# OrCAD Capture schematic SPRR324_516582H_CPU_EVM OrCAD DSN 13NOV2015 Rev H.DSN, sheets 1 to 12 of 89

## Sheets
1 SH01 - TITLE PAGE: title: VAYU EVM; rev: H; note: 516582-0001
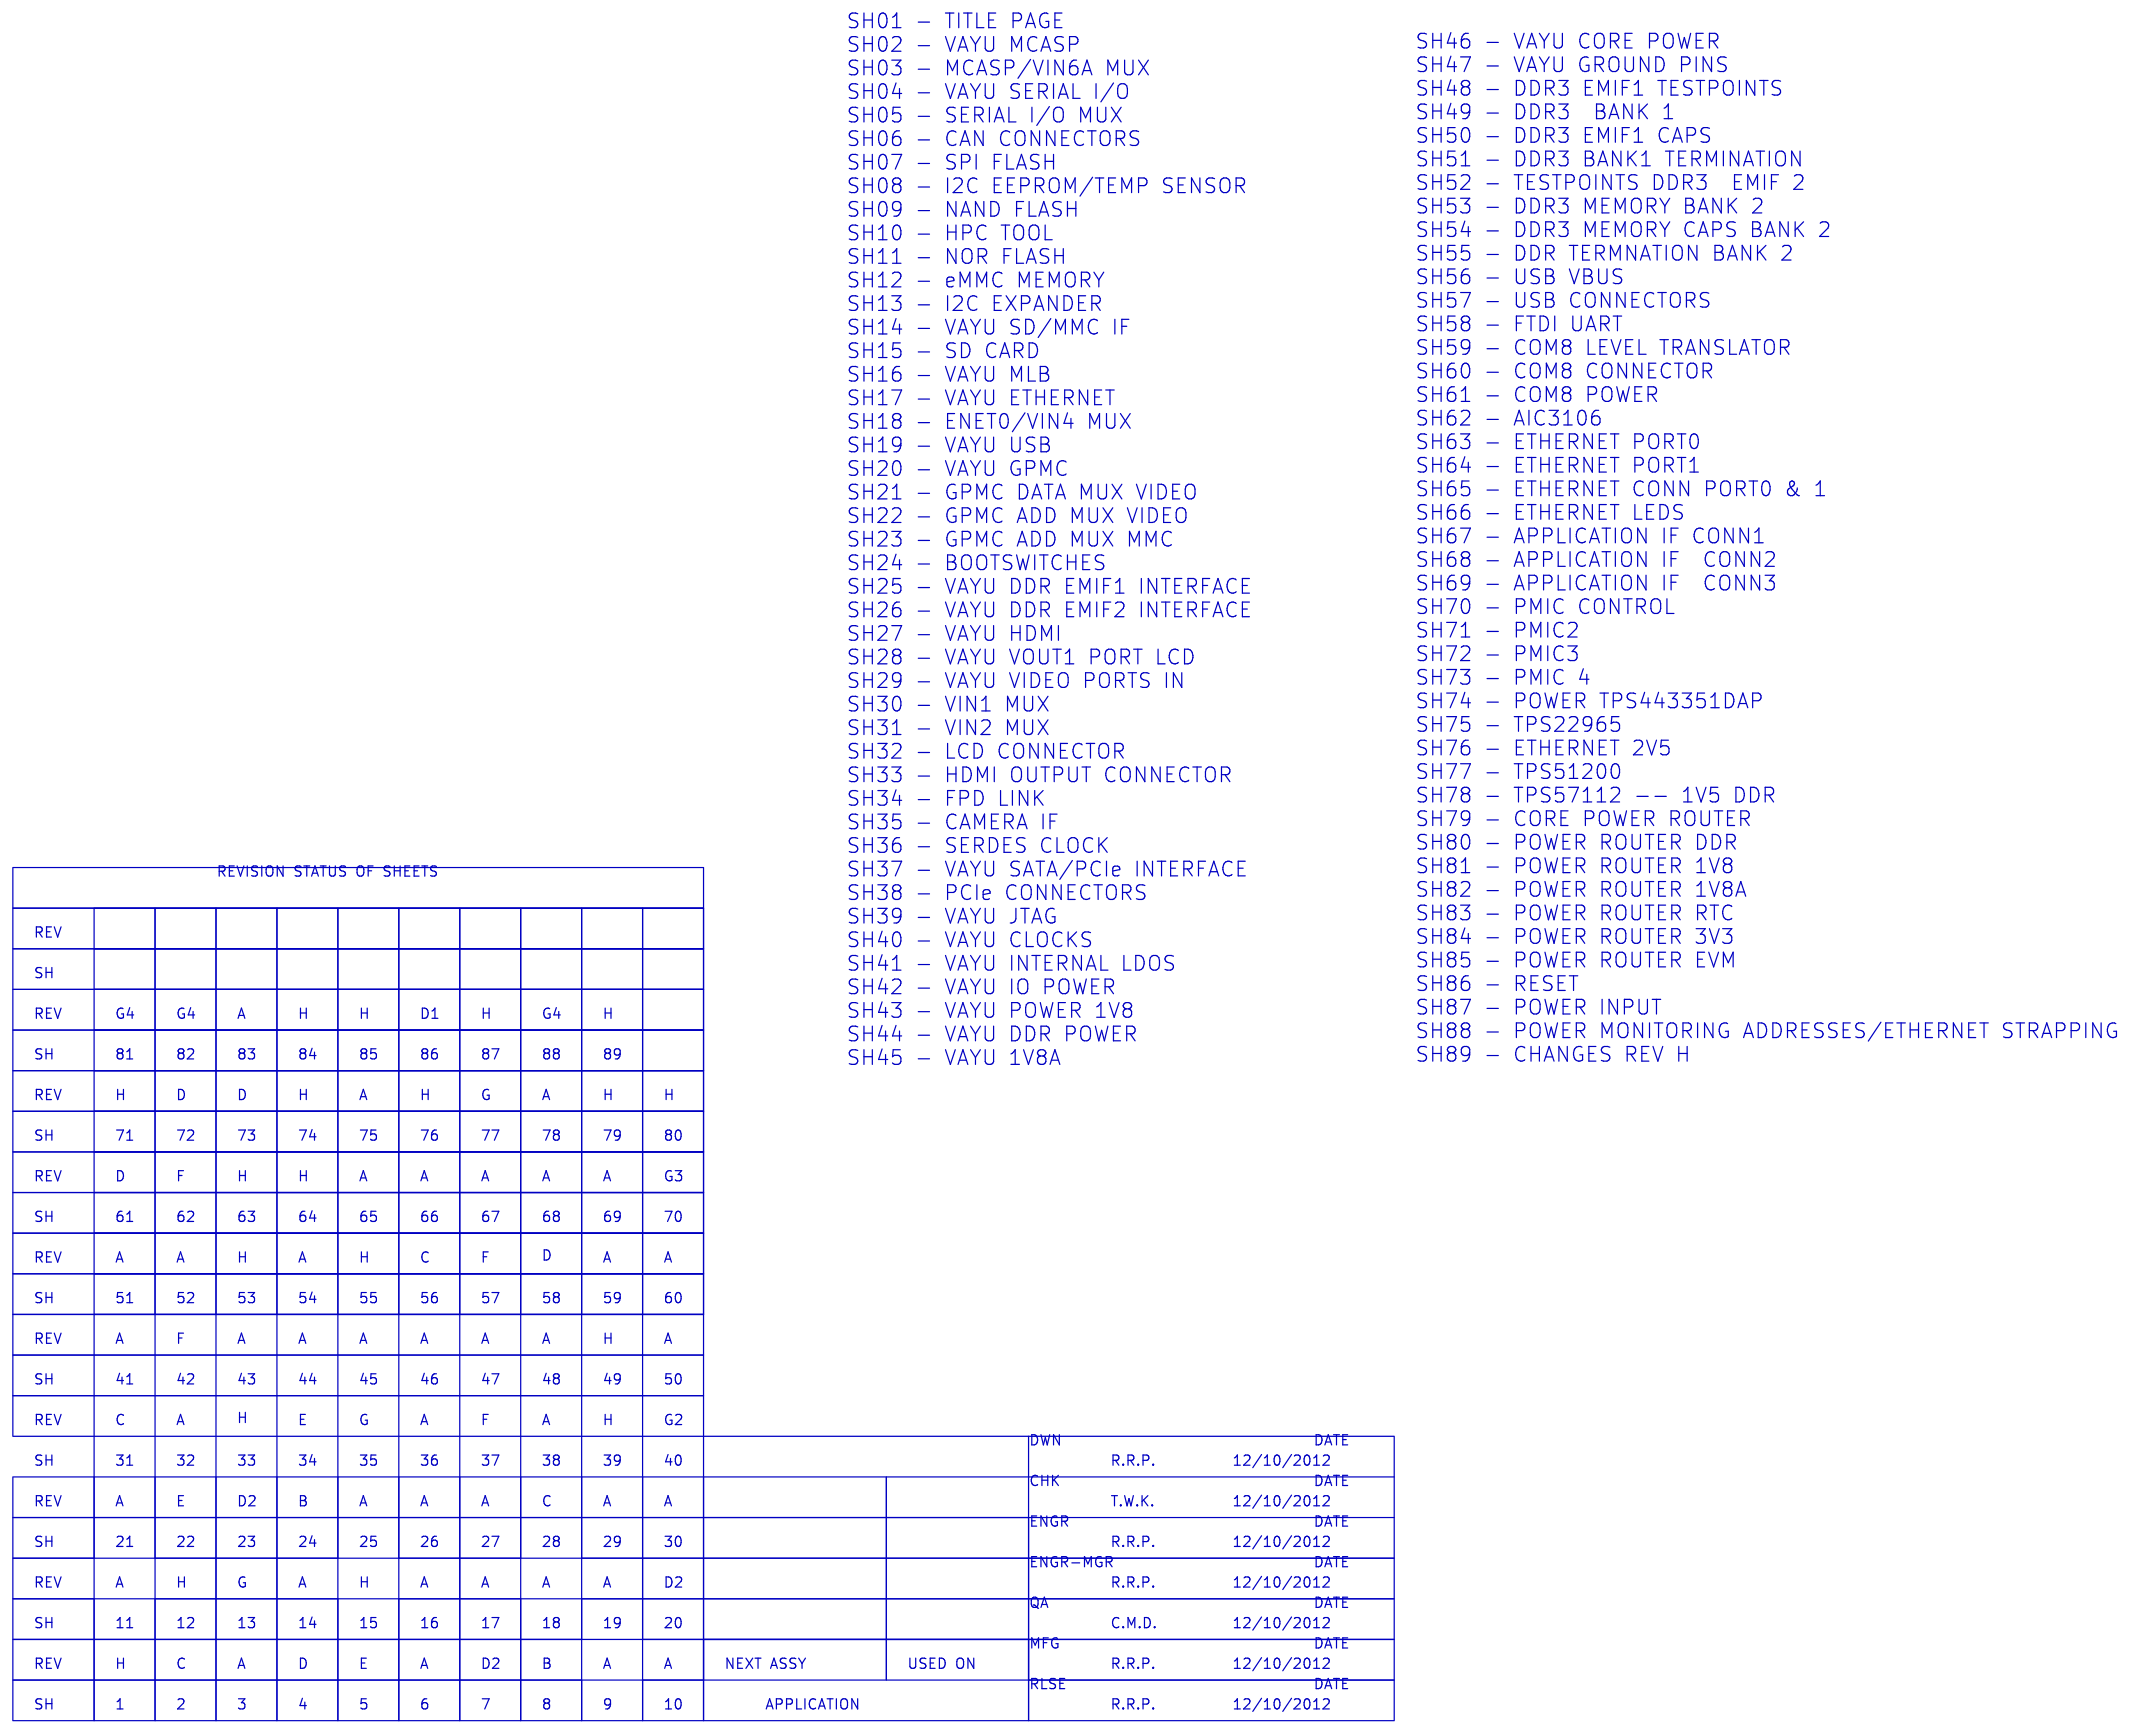
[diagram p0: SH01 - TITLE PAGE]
2 SH02 - VAYU MCASP: size B; rev: C
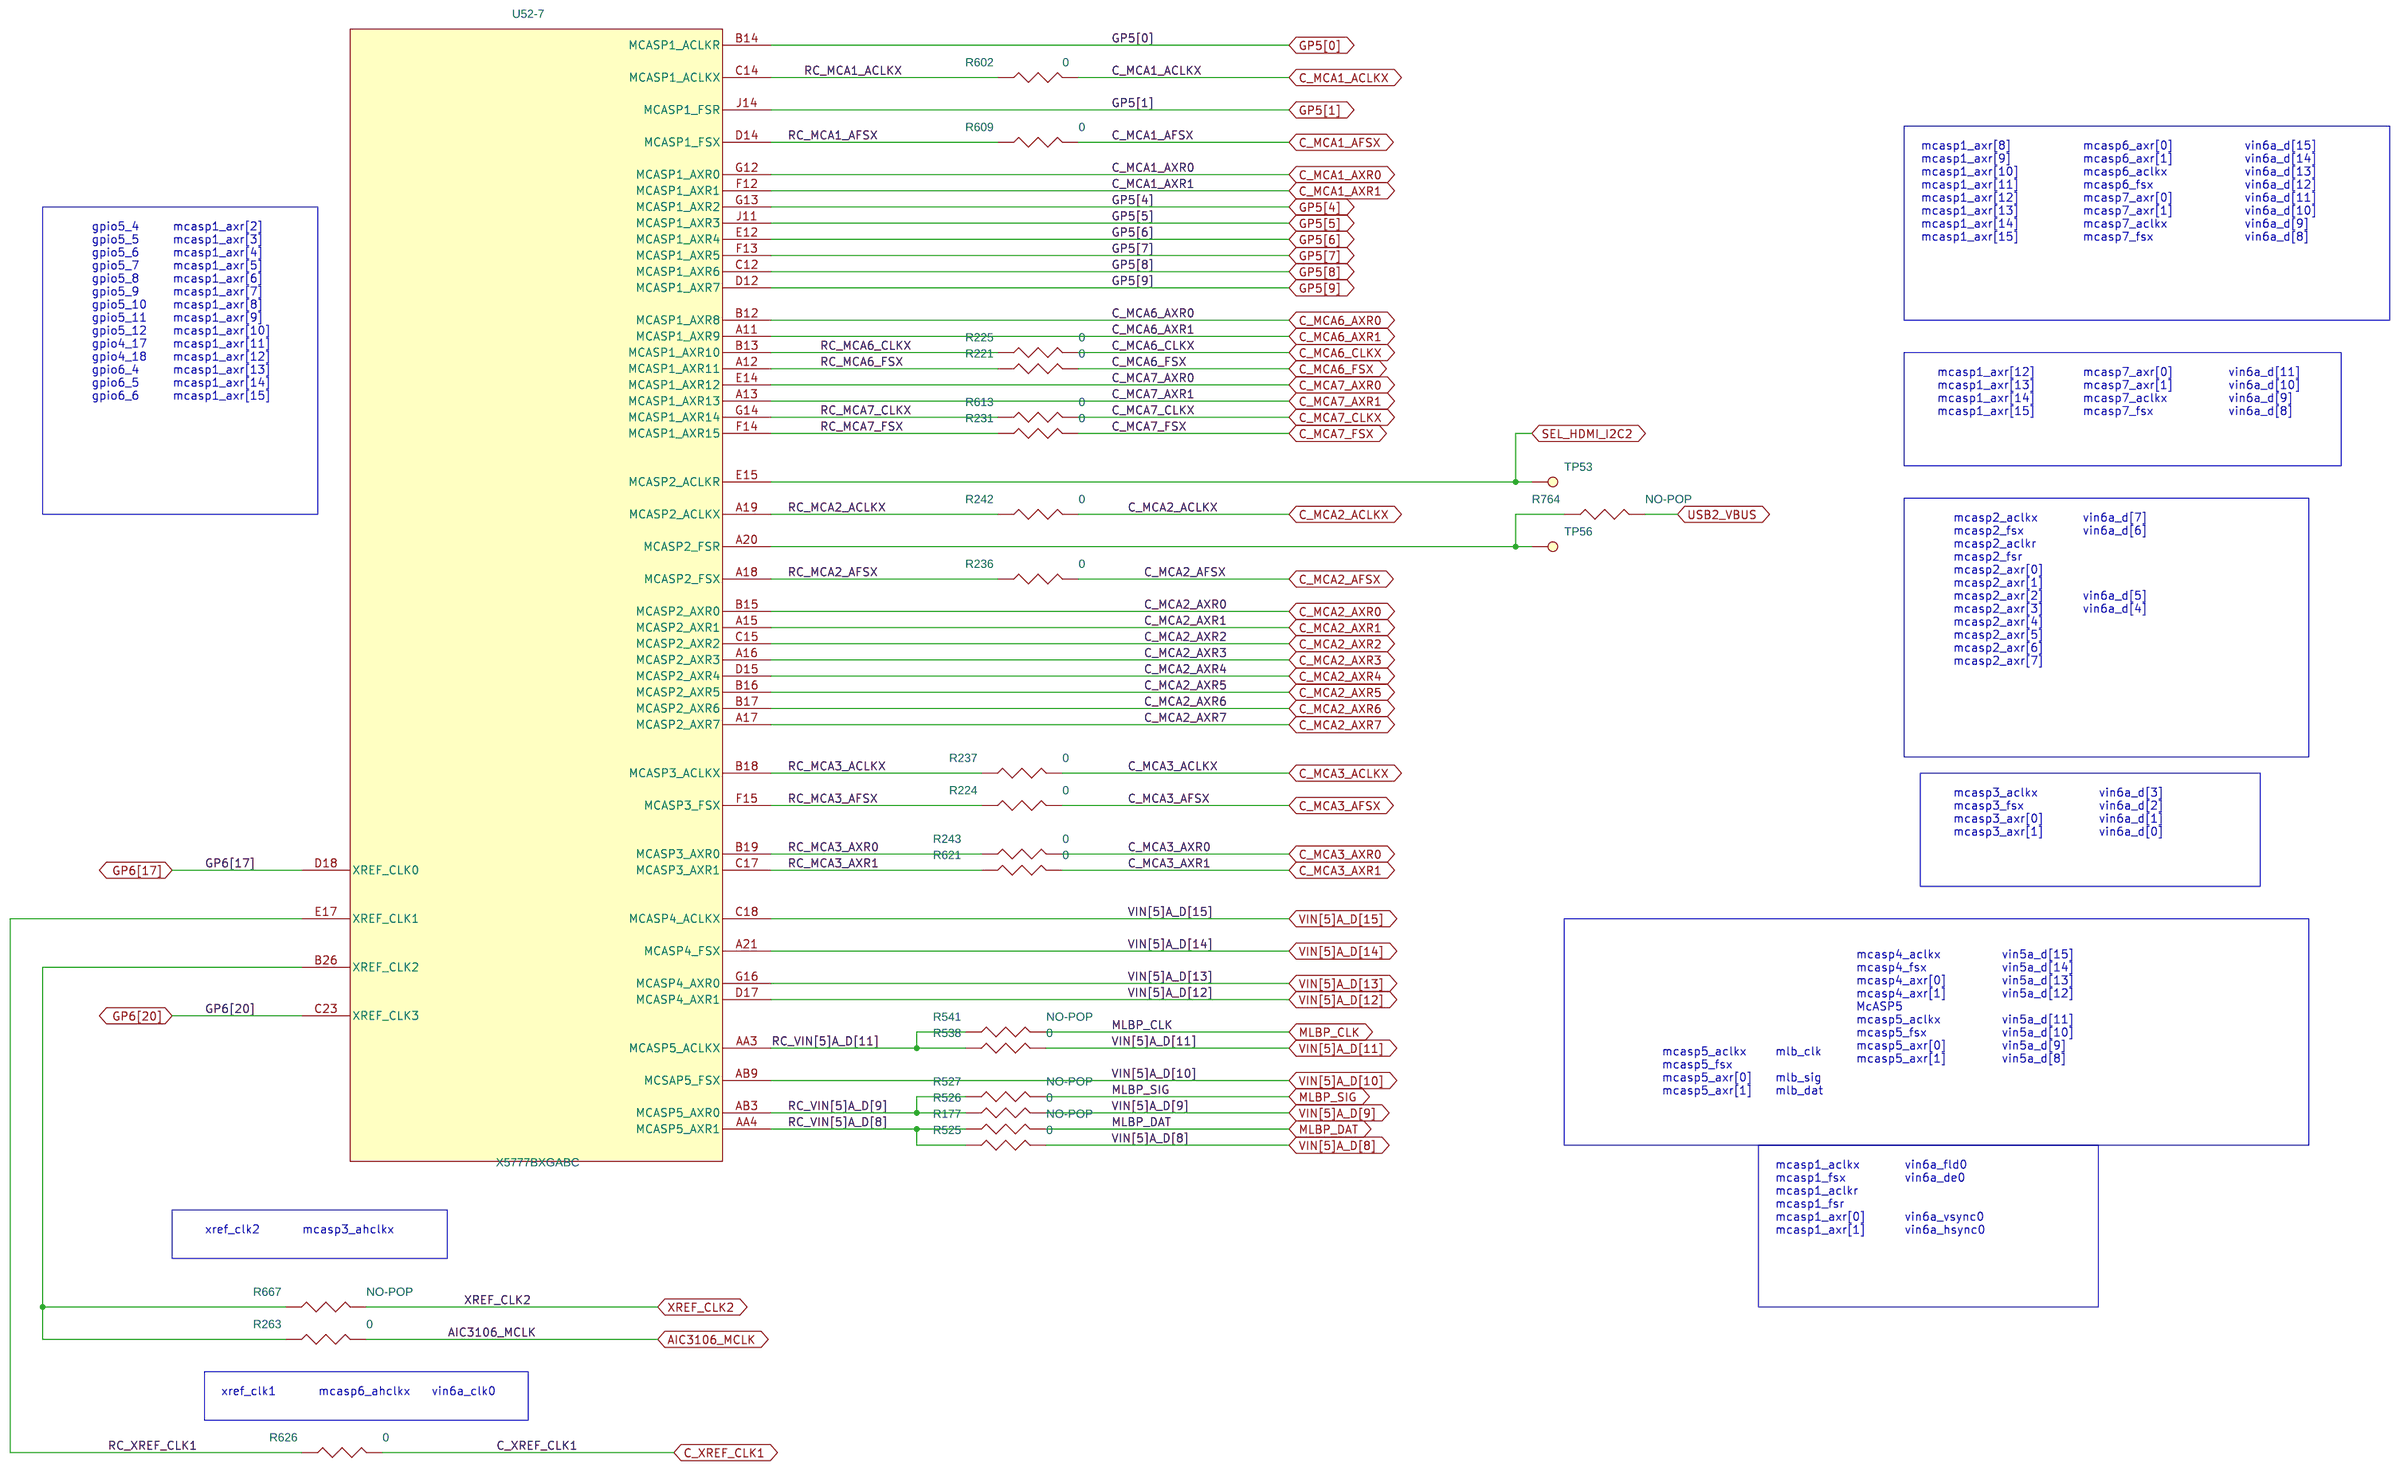
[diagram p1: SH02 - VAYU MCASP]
3 SH06 - CAN CONNECTORS: size B; rev: A
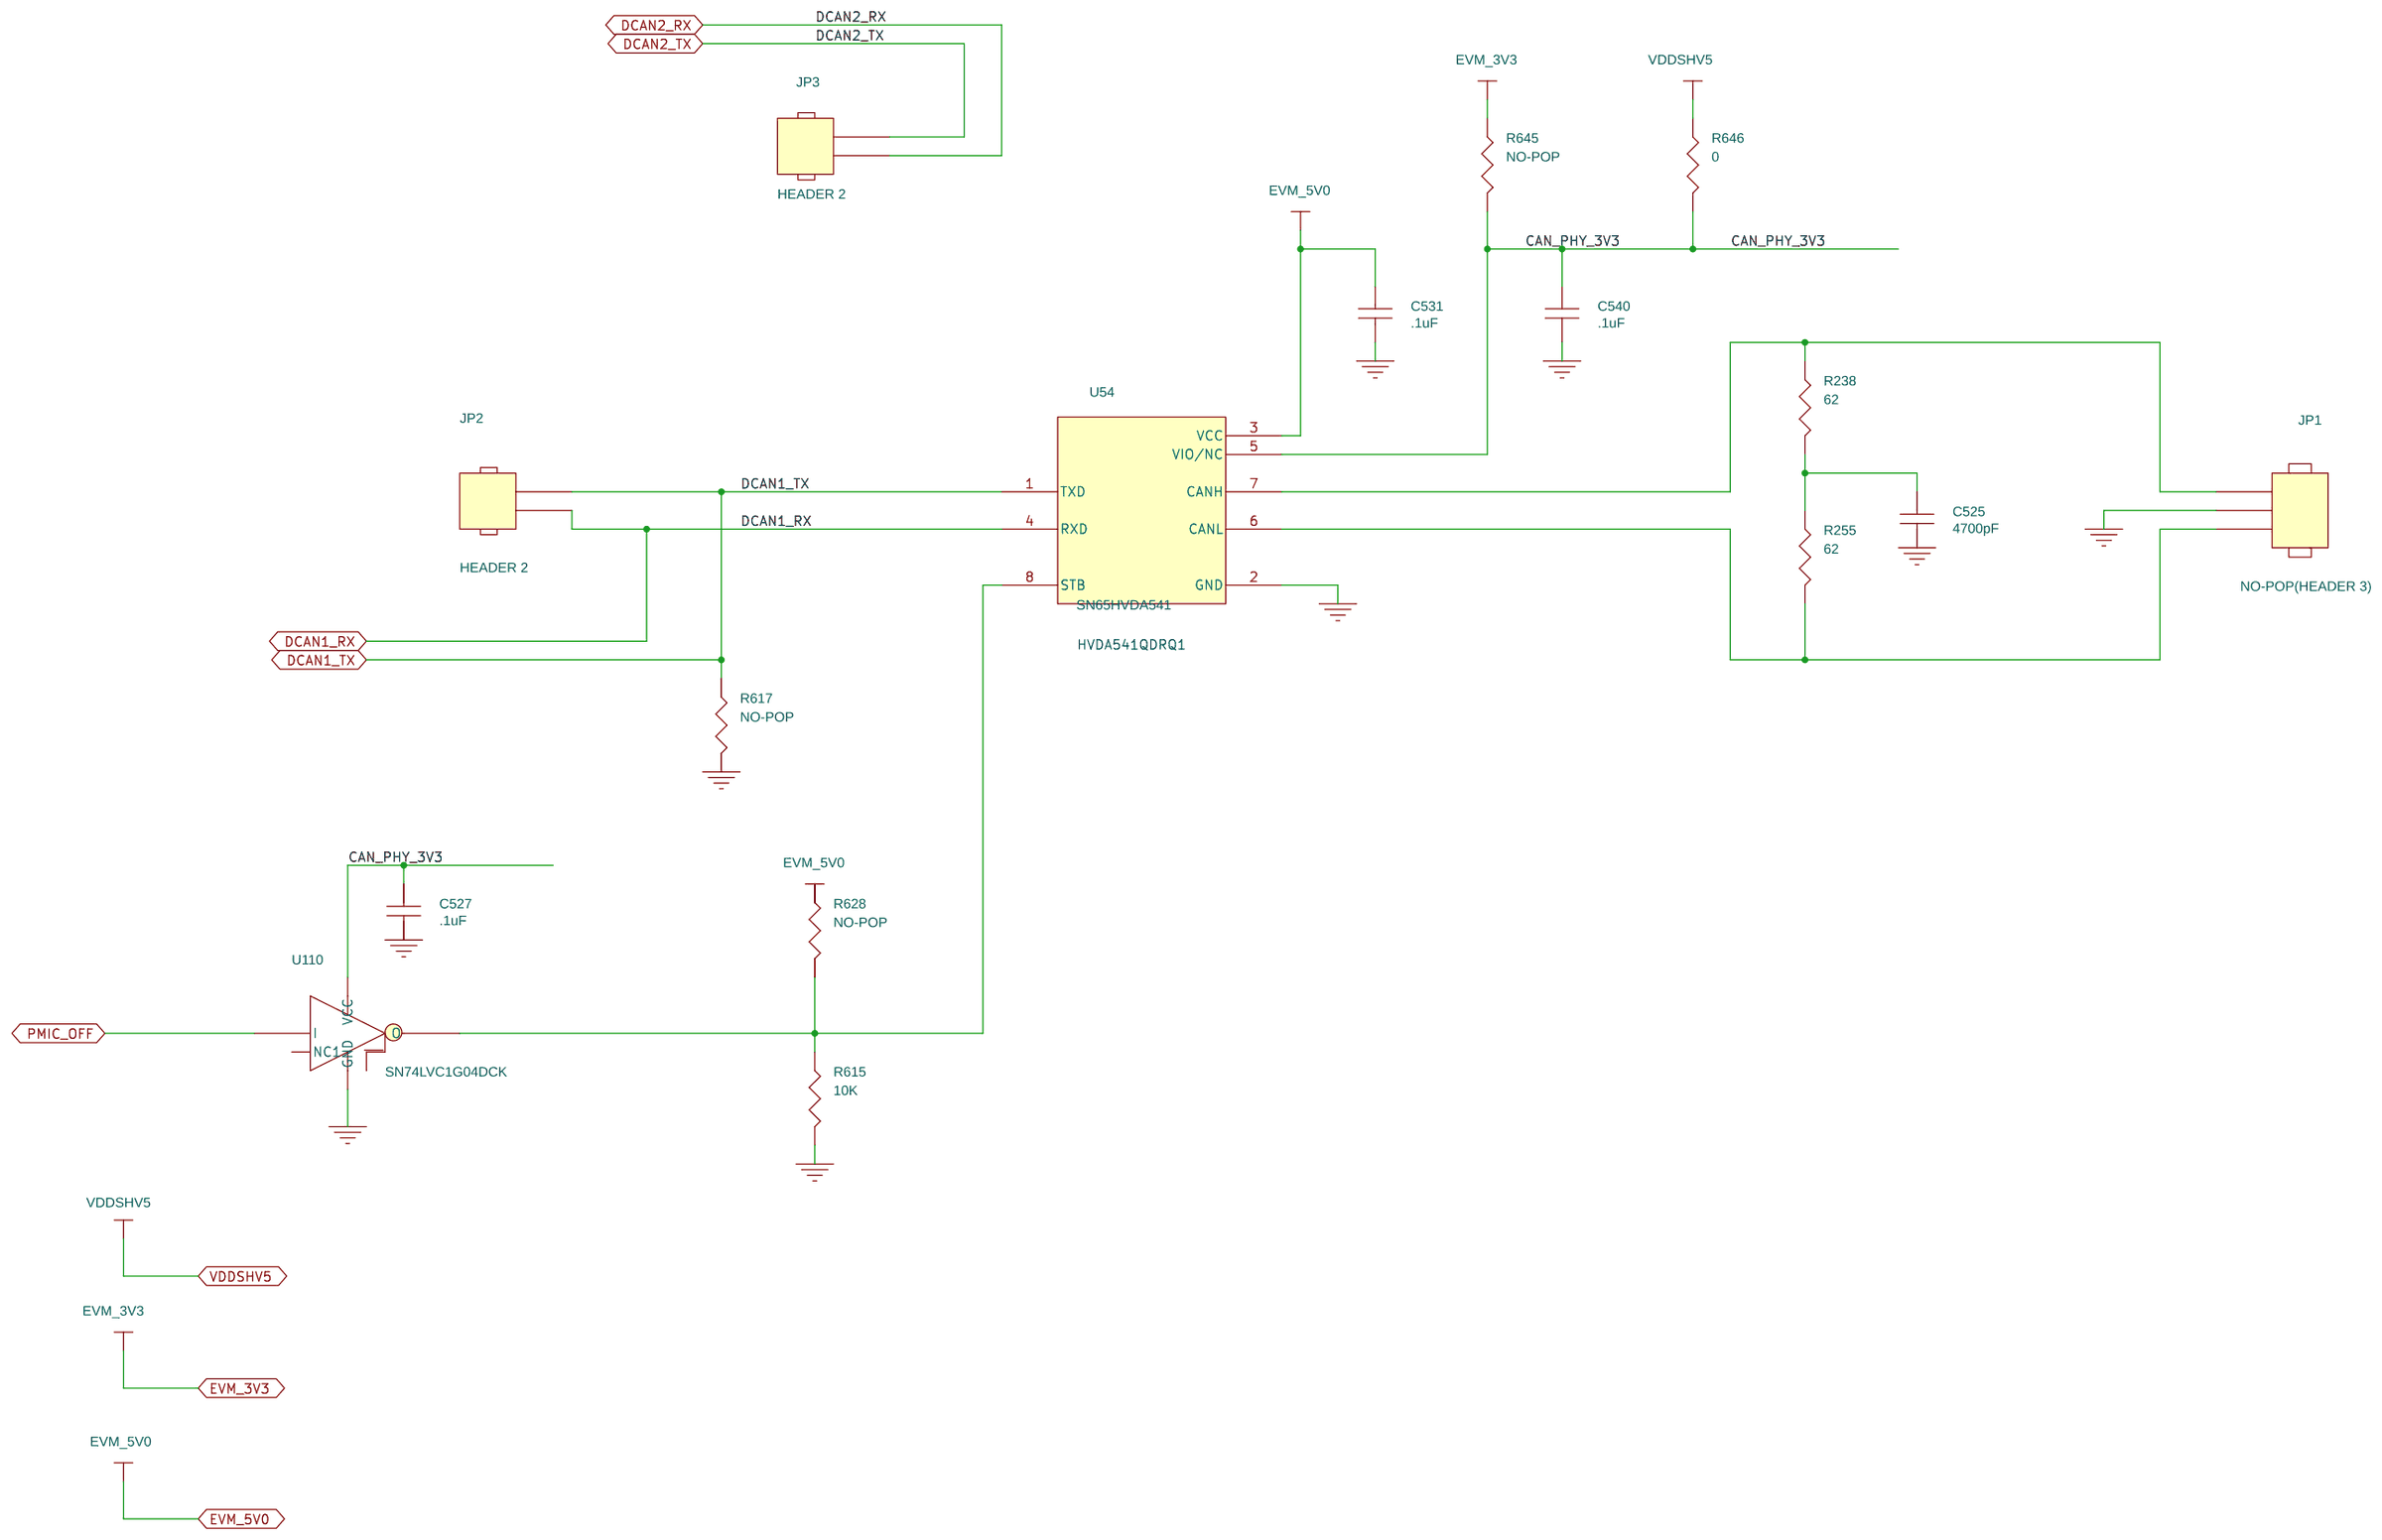
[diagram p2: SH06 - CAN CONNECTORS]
4 SH07 - SPI FLASH: size B; rev: D2
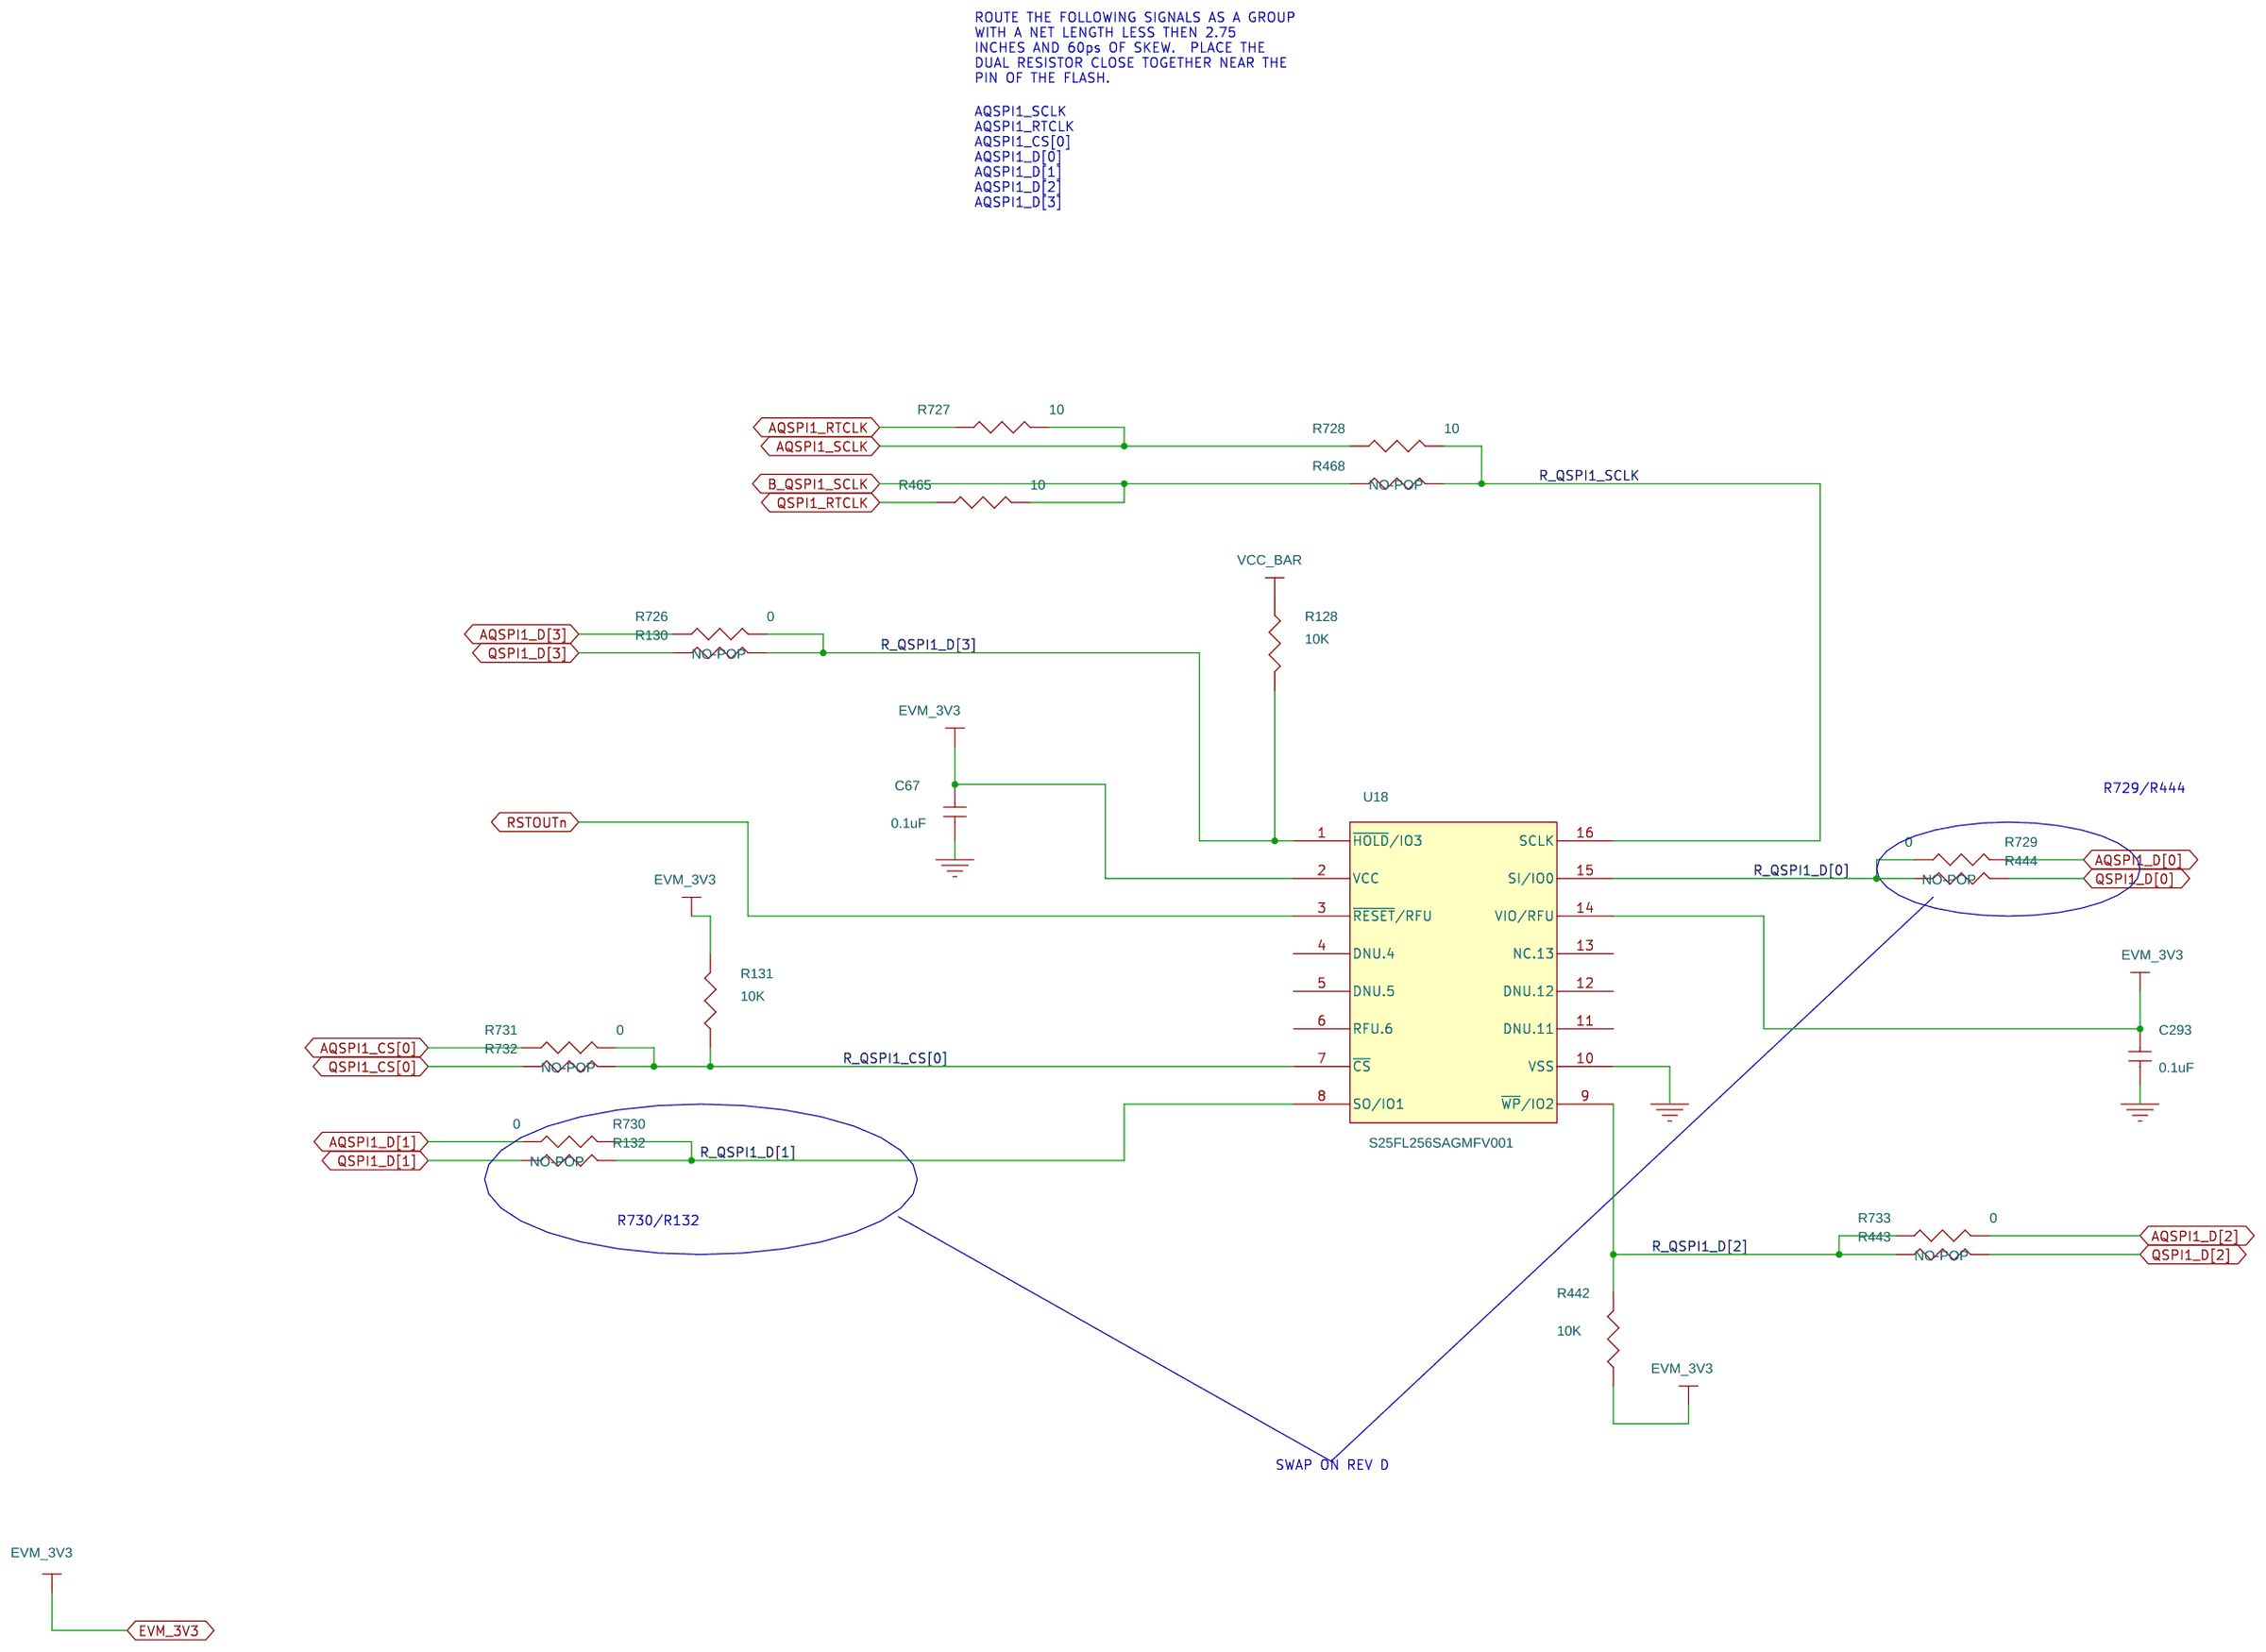
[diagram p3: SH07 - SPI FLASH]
5 SH09 - NAND FLASH: size B; rev: A
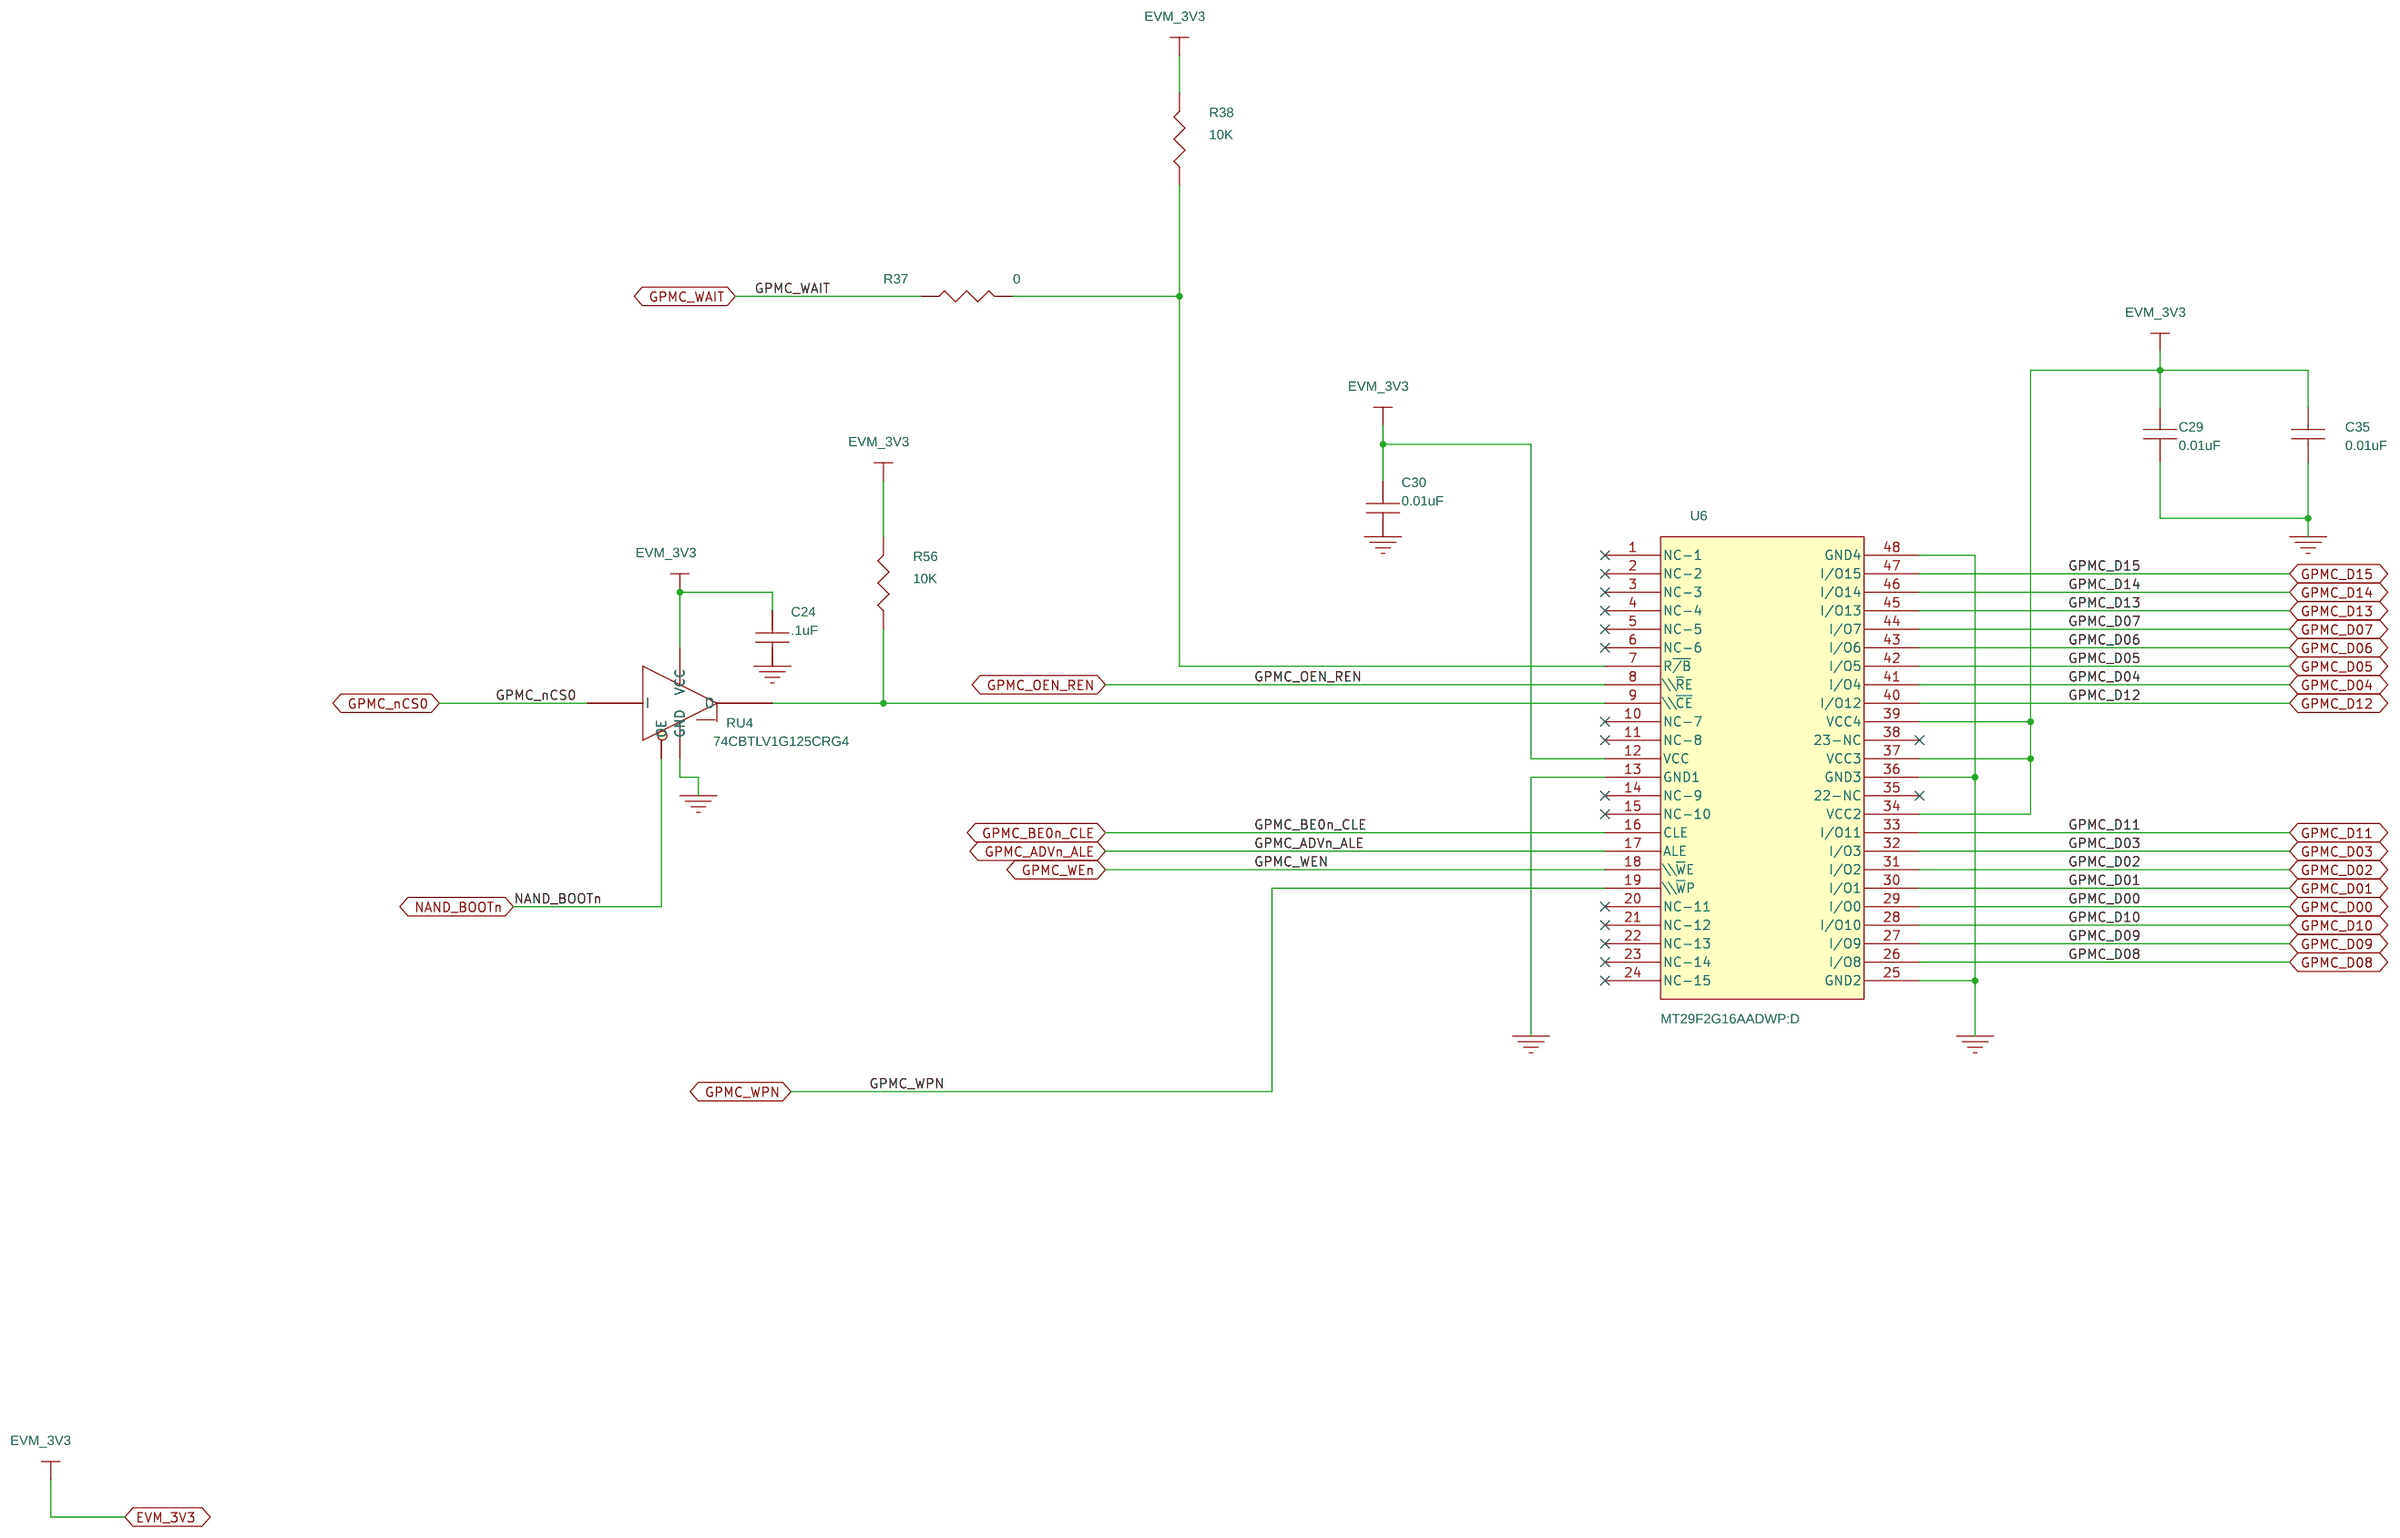
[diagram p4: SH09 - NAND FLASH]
6 SH10 - HPC TOOL: rev: A
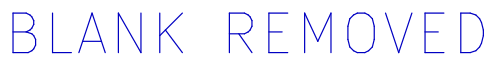
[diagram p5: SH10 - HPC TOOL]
7 SH11 - NOR FLASH: size B; rev: A
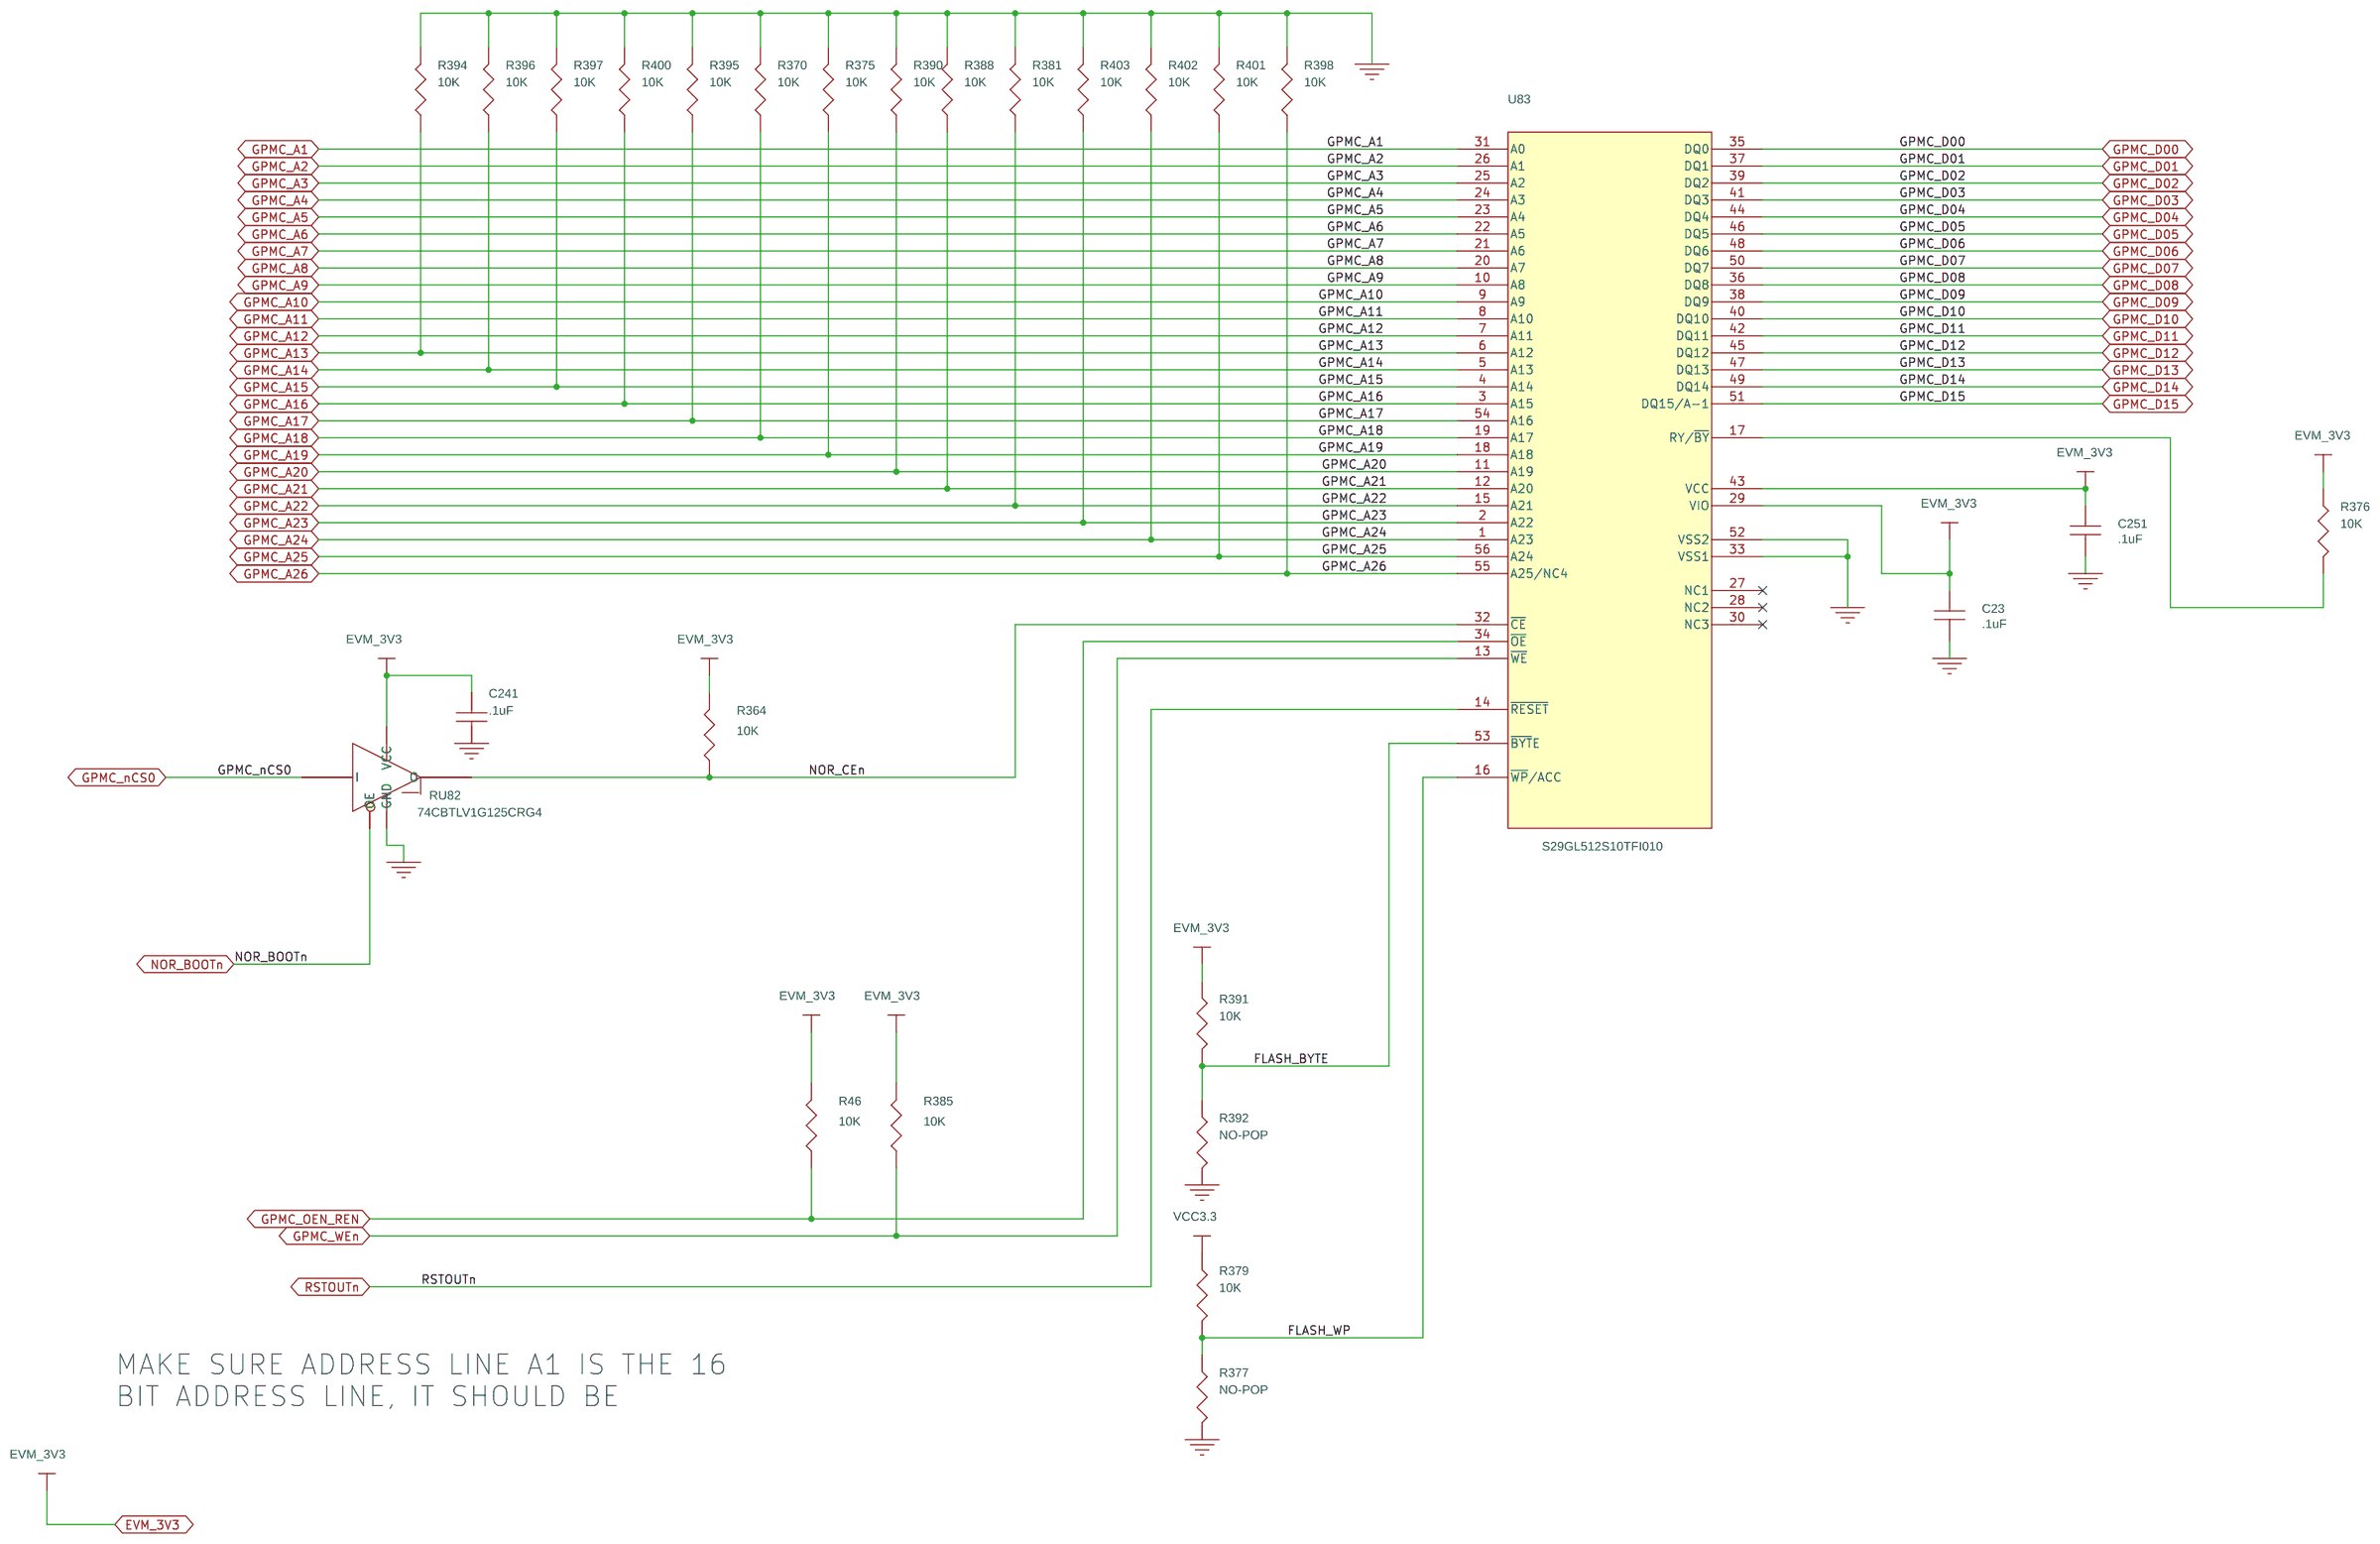
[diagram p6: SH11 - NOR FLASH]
8 SH12 - eMMC MEMORY: size B
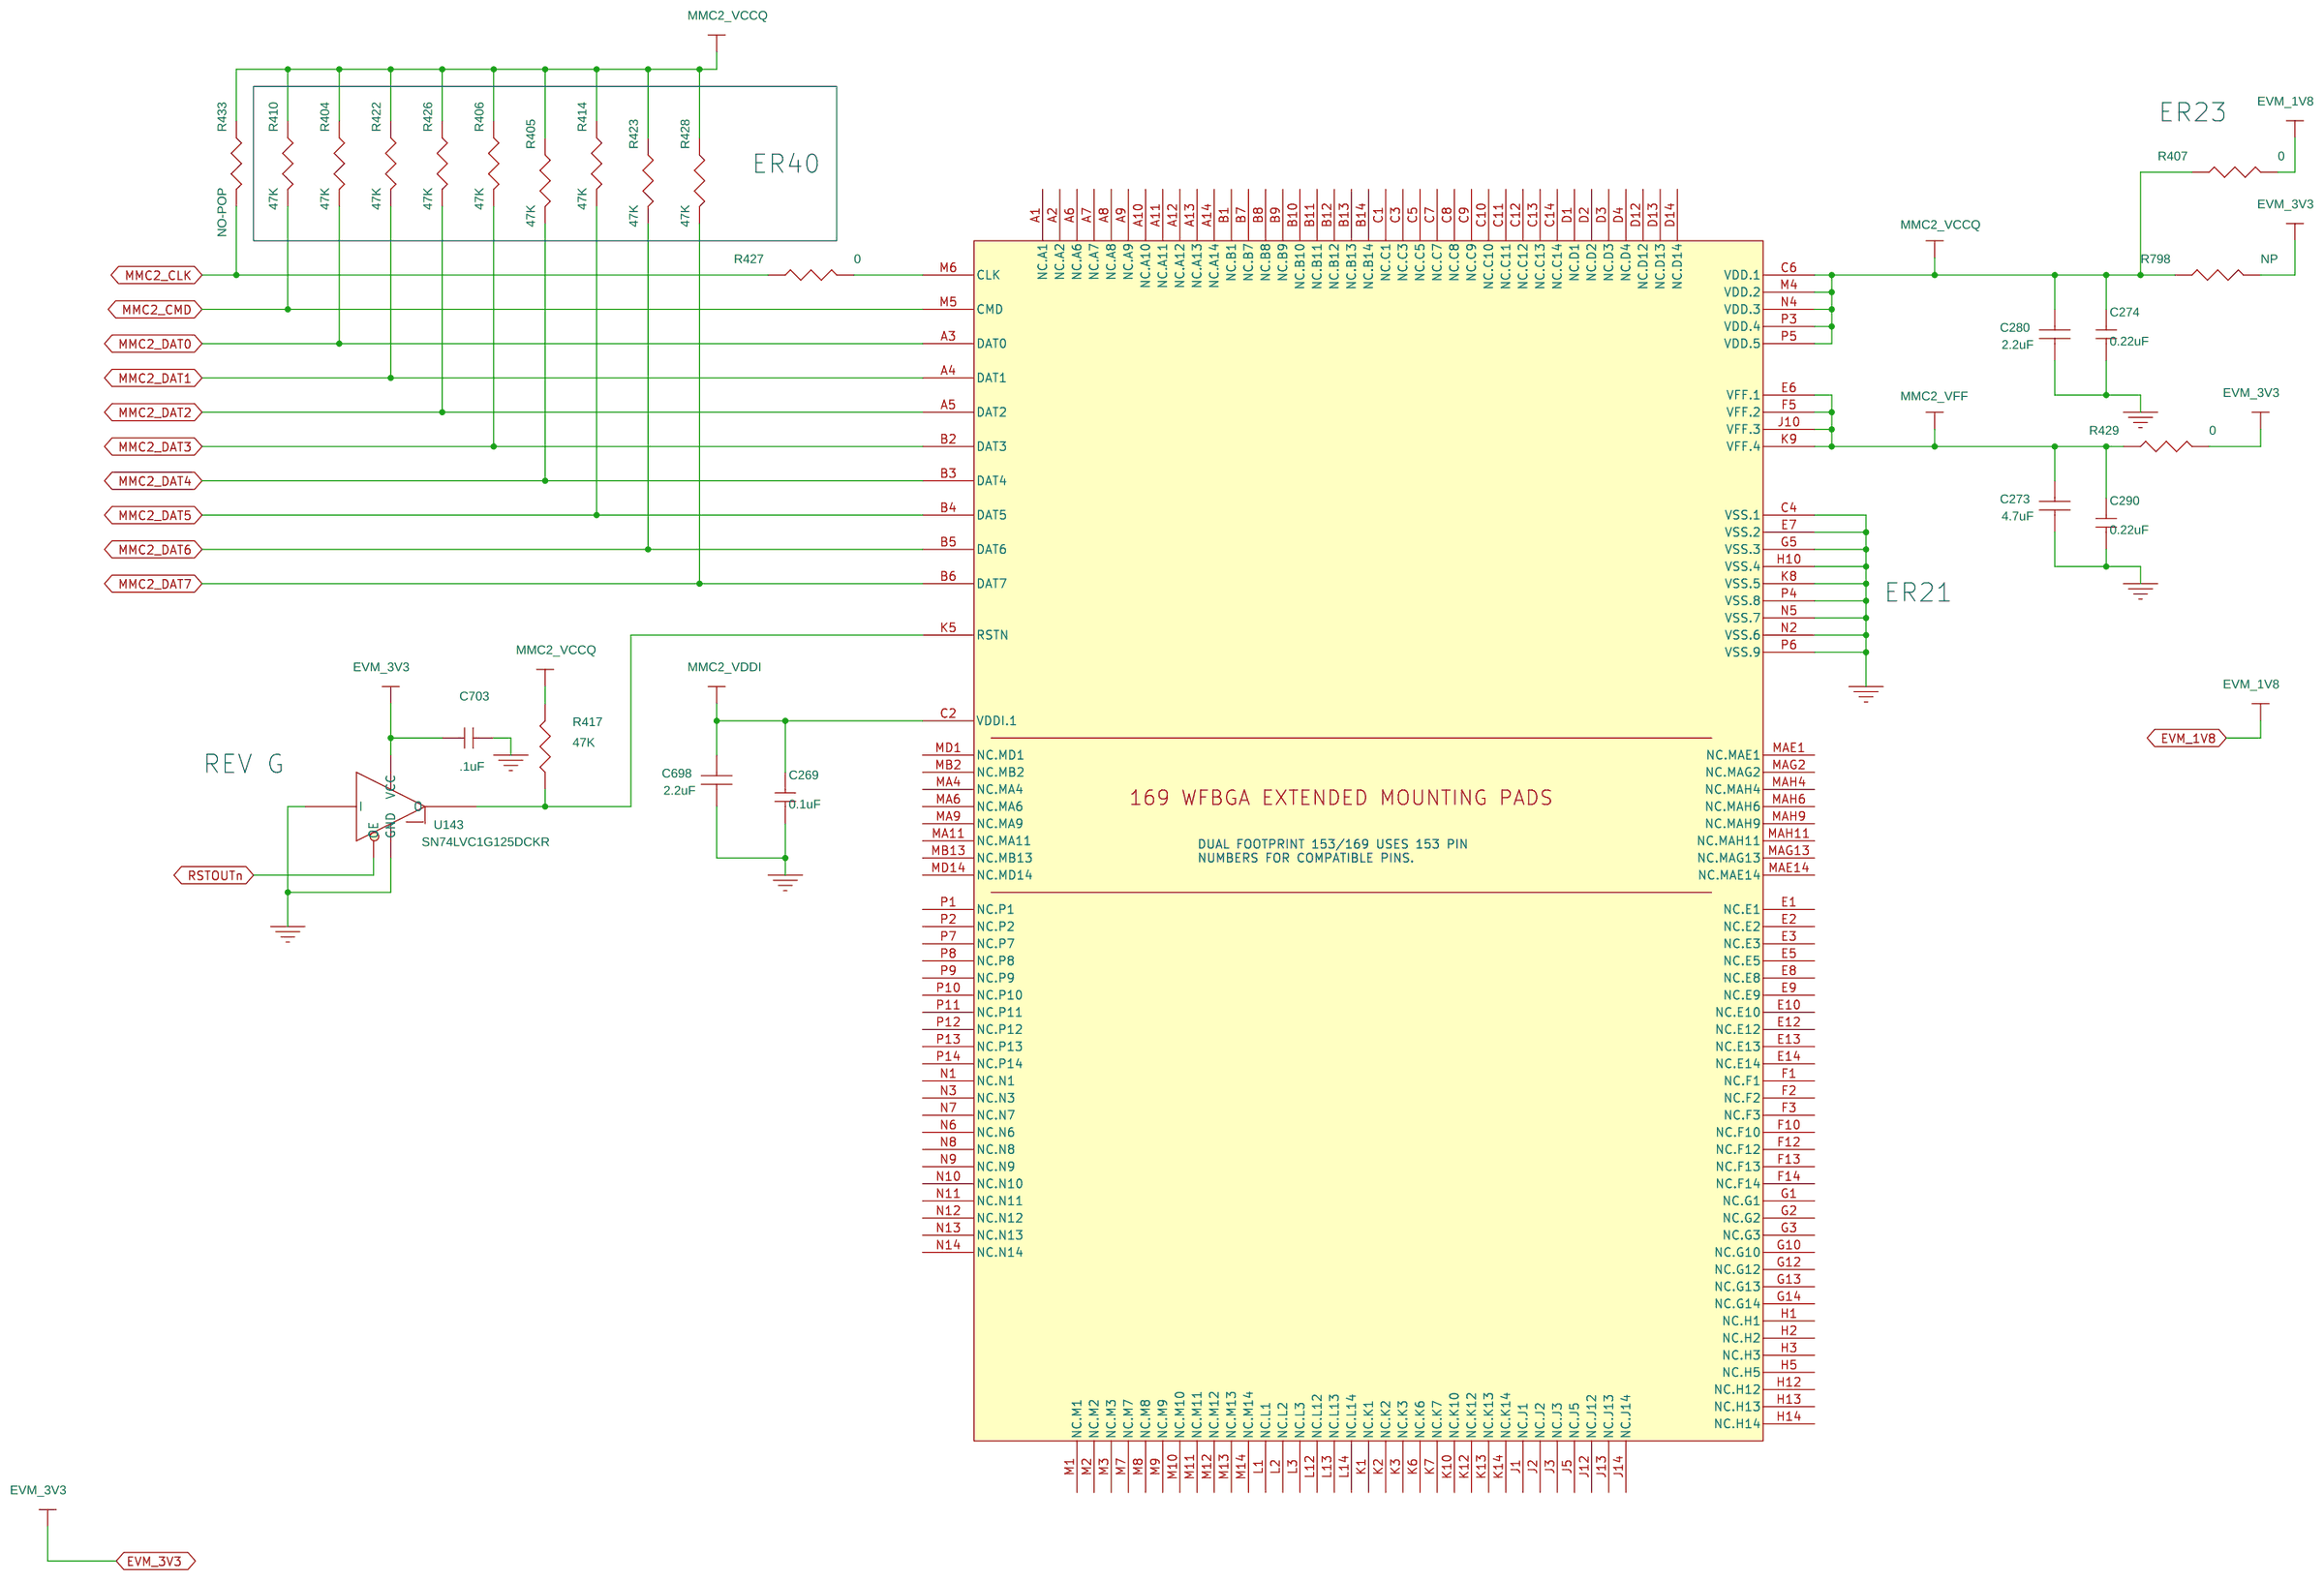
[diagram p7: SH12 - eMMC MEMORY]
9 SH13 - I2C EXPANDER: size B; rev: G
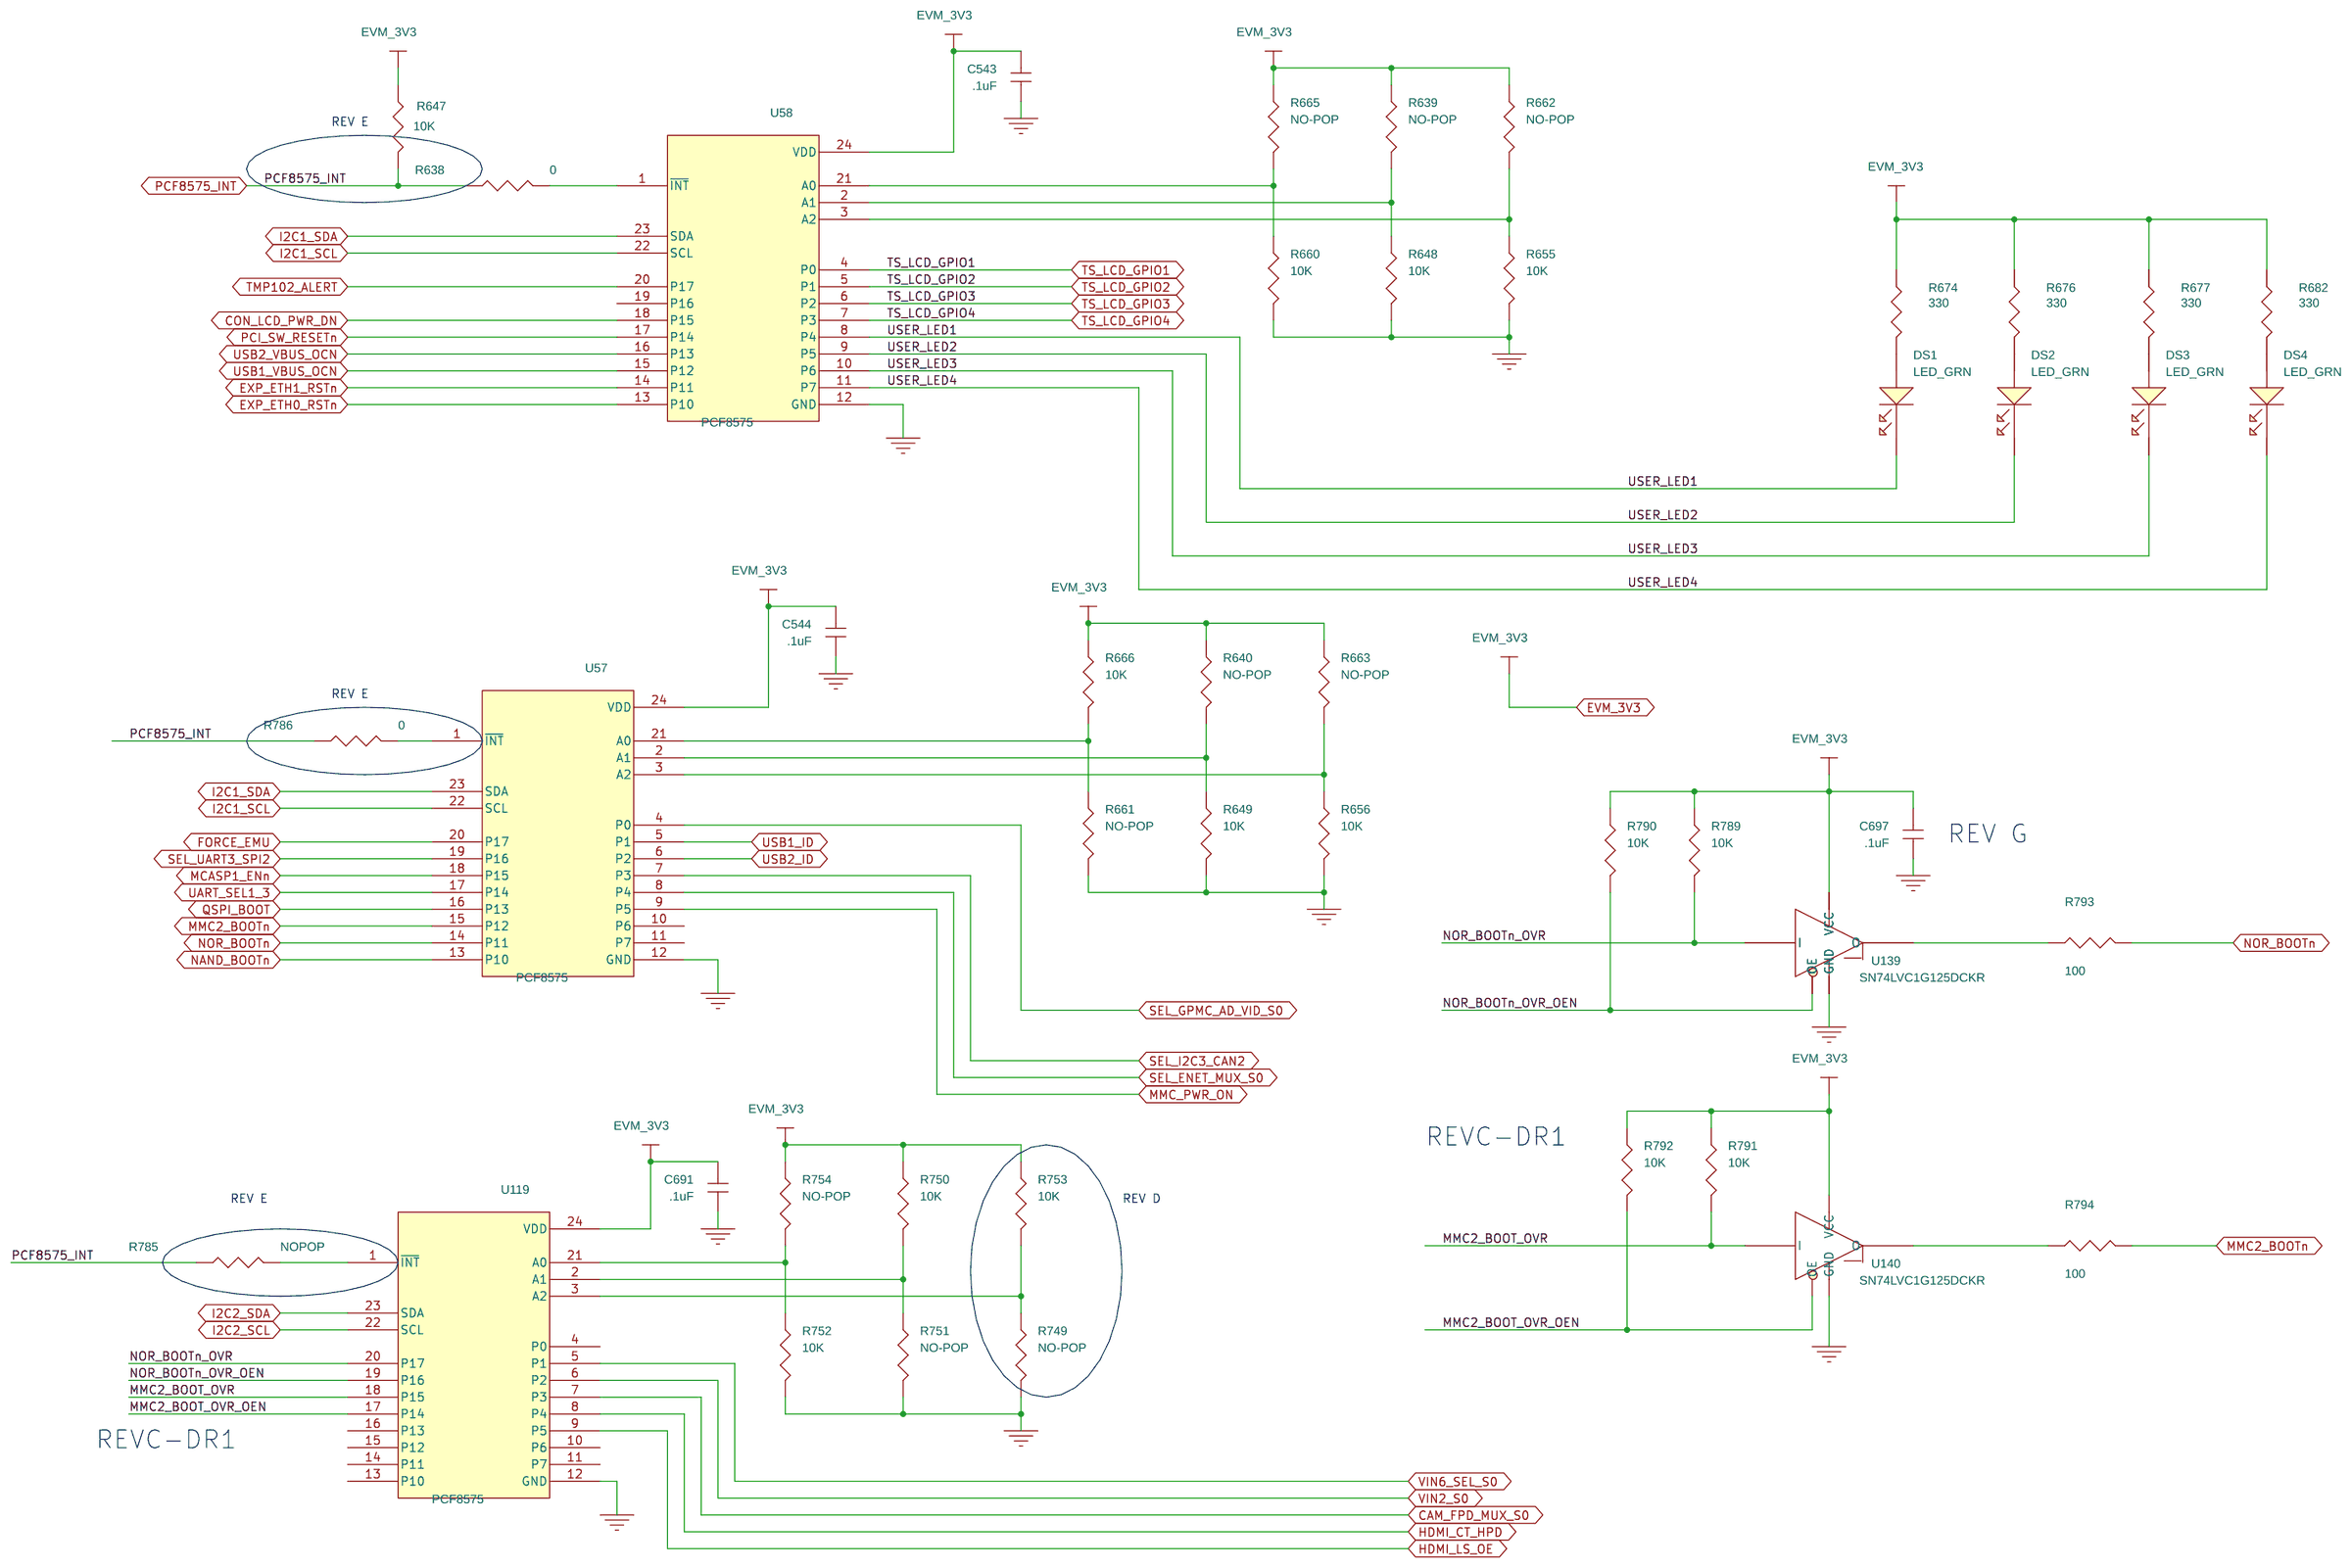
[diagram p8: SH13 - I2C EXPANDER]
10 SH15 - SD CARD: size B
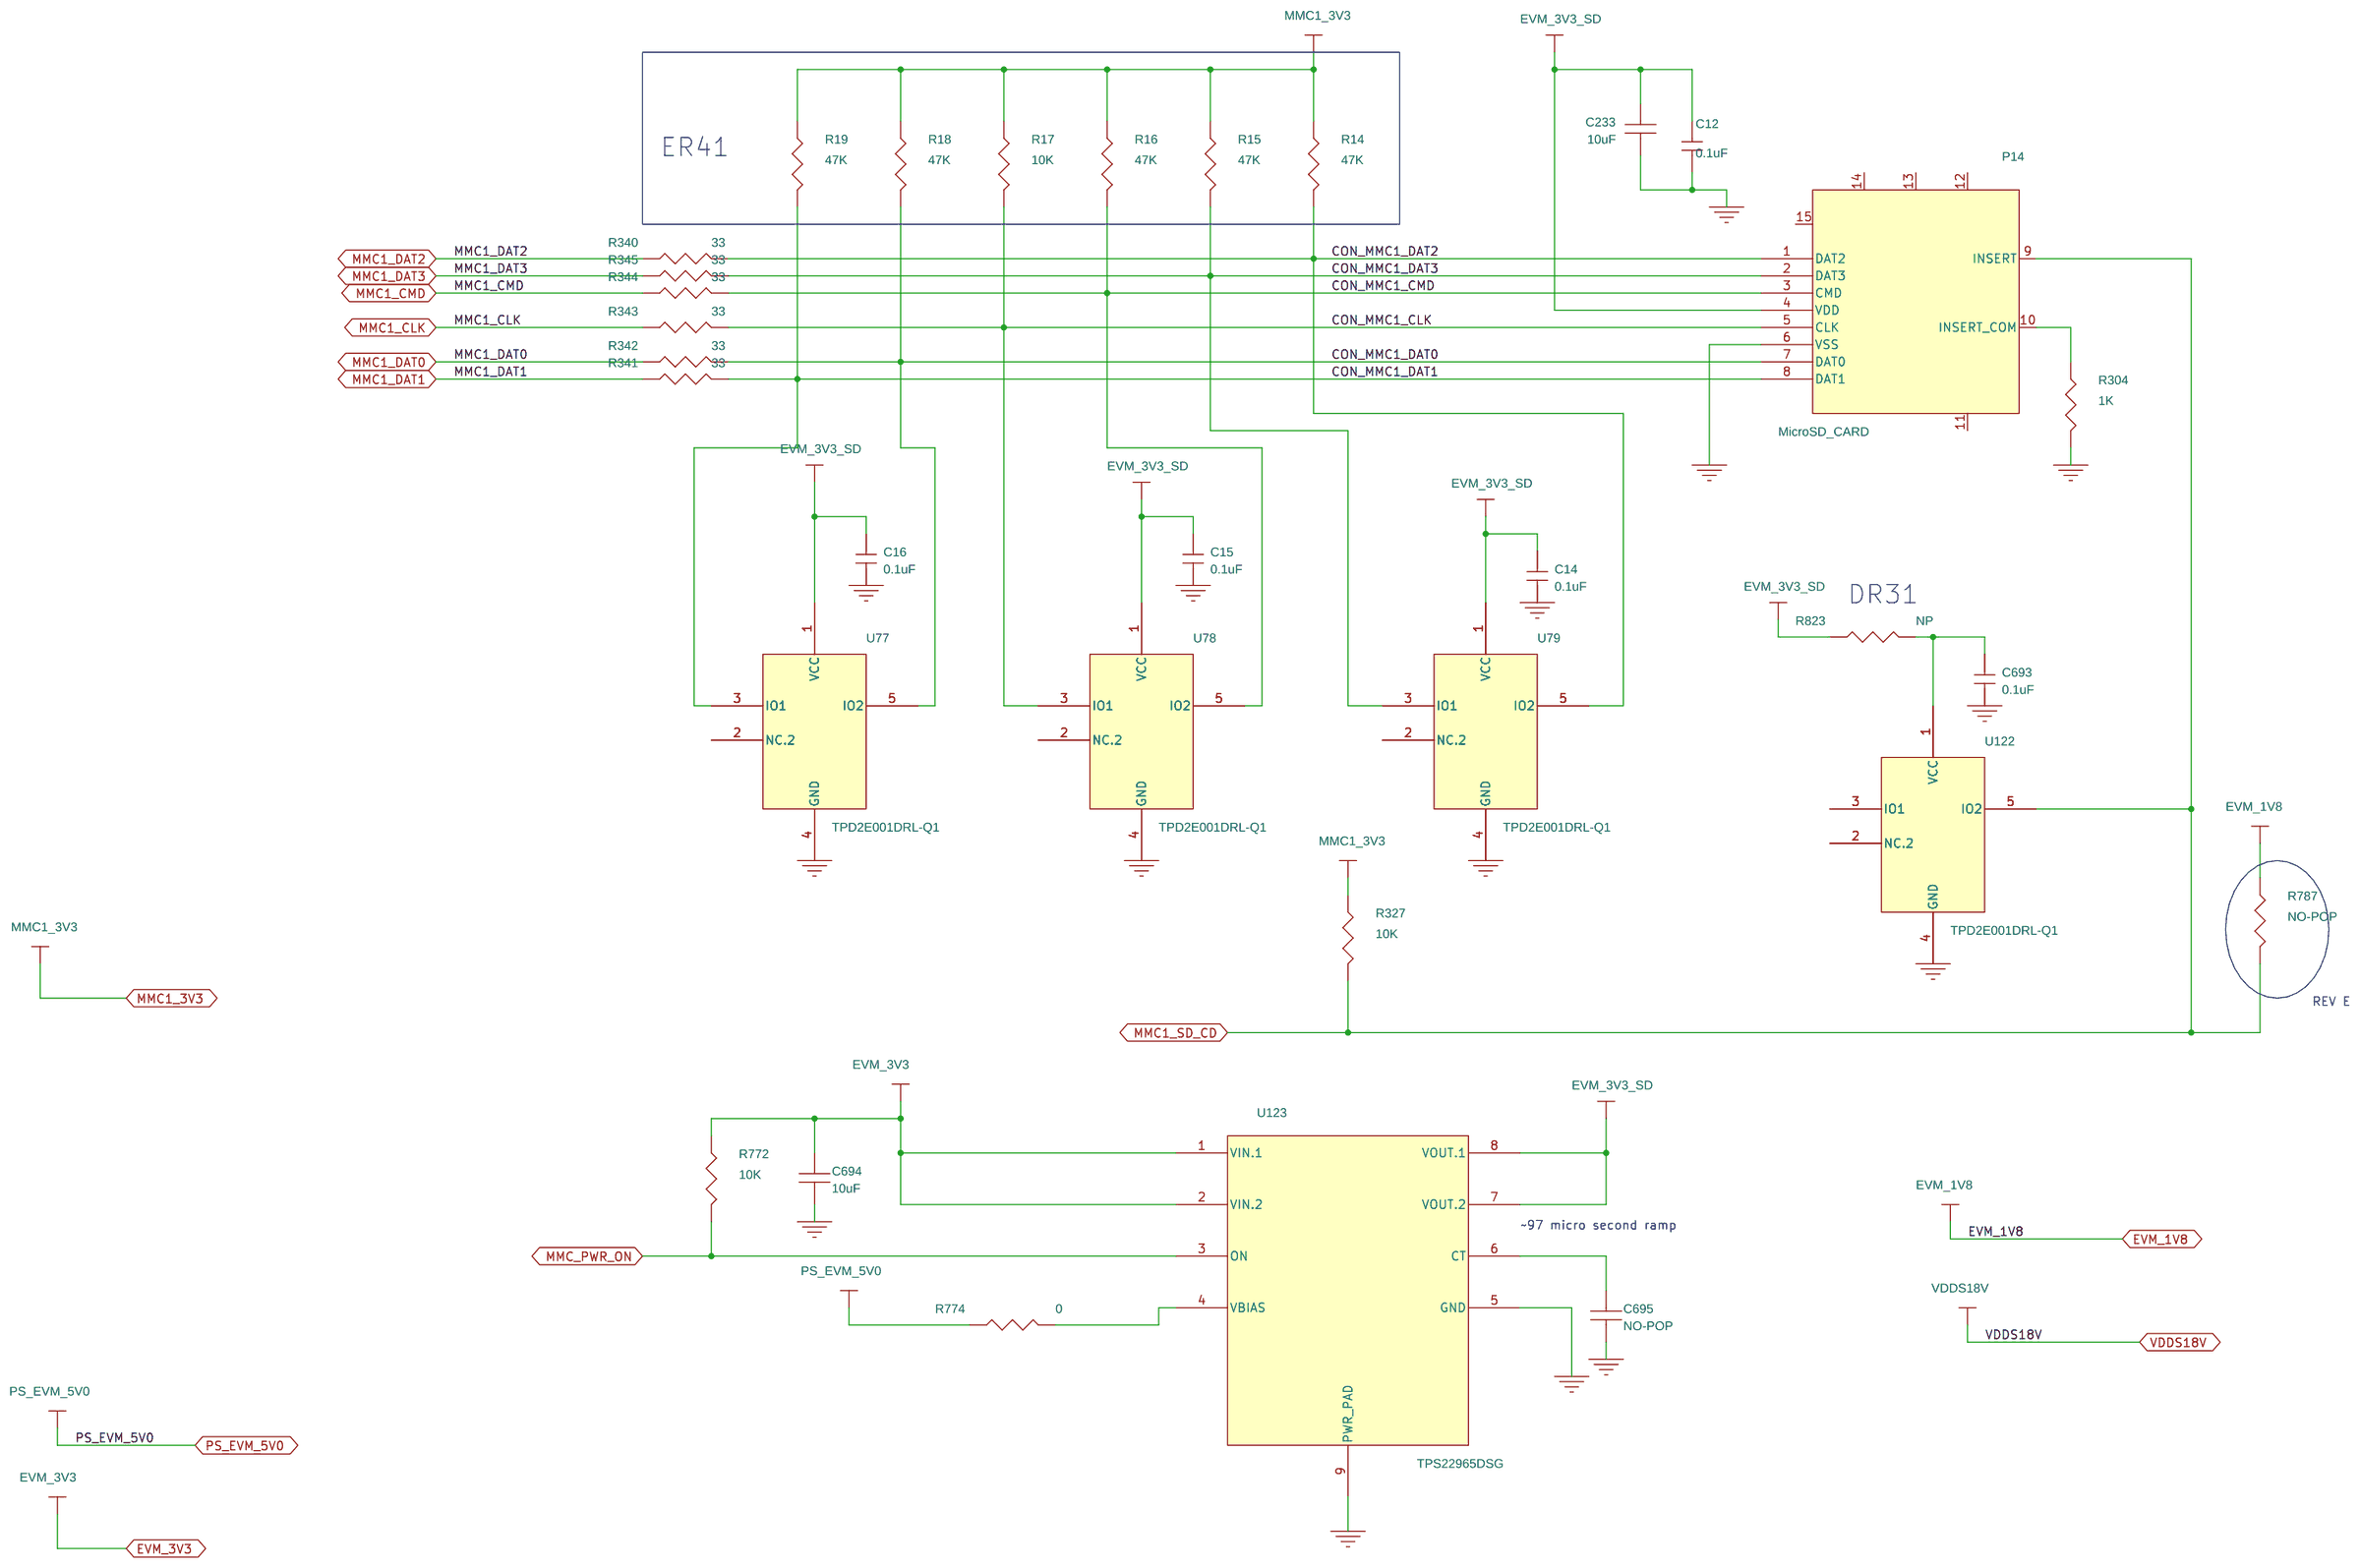
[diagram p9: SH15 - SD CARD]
11 SH16 - VAYU MLB: size B; rev: A
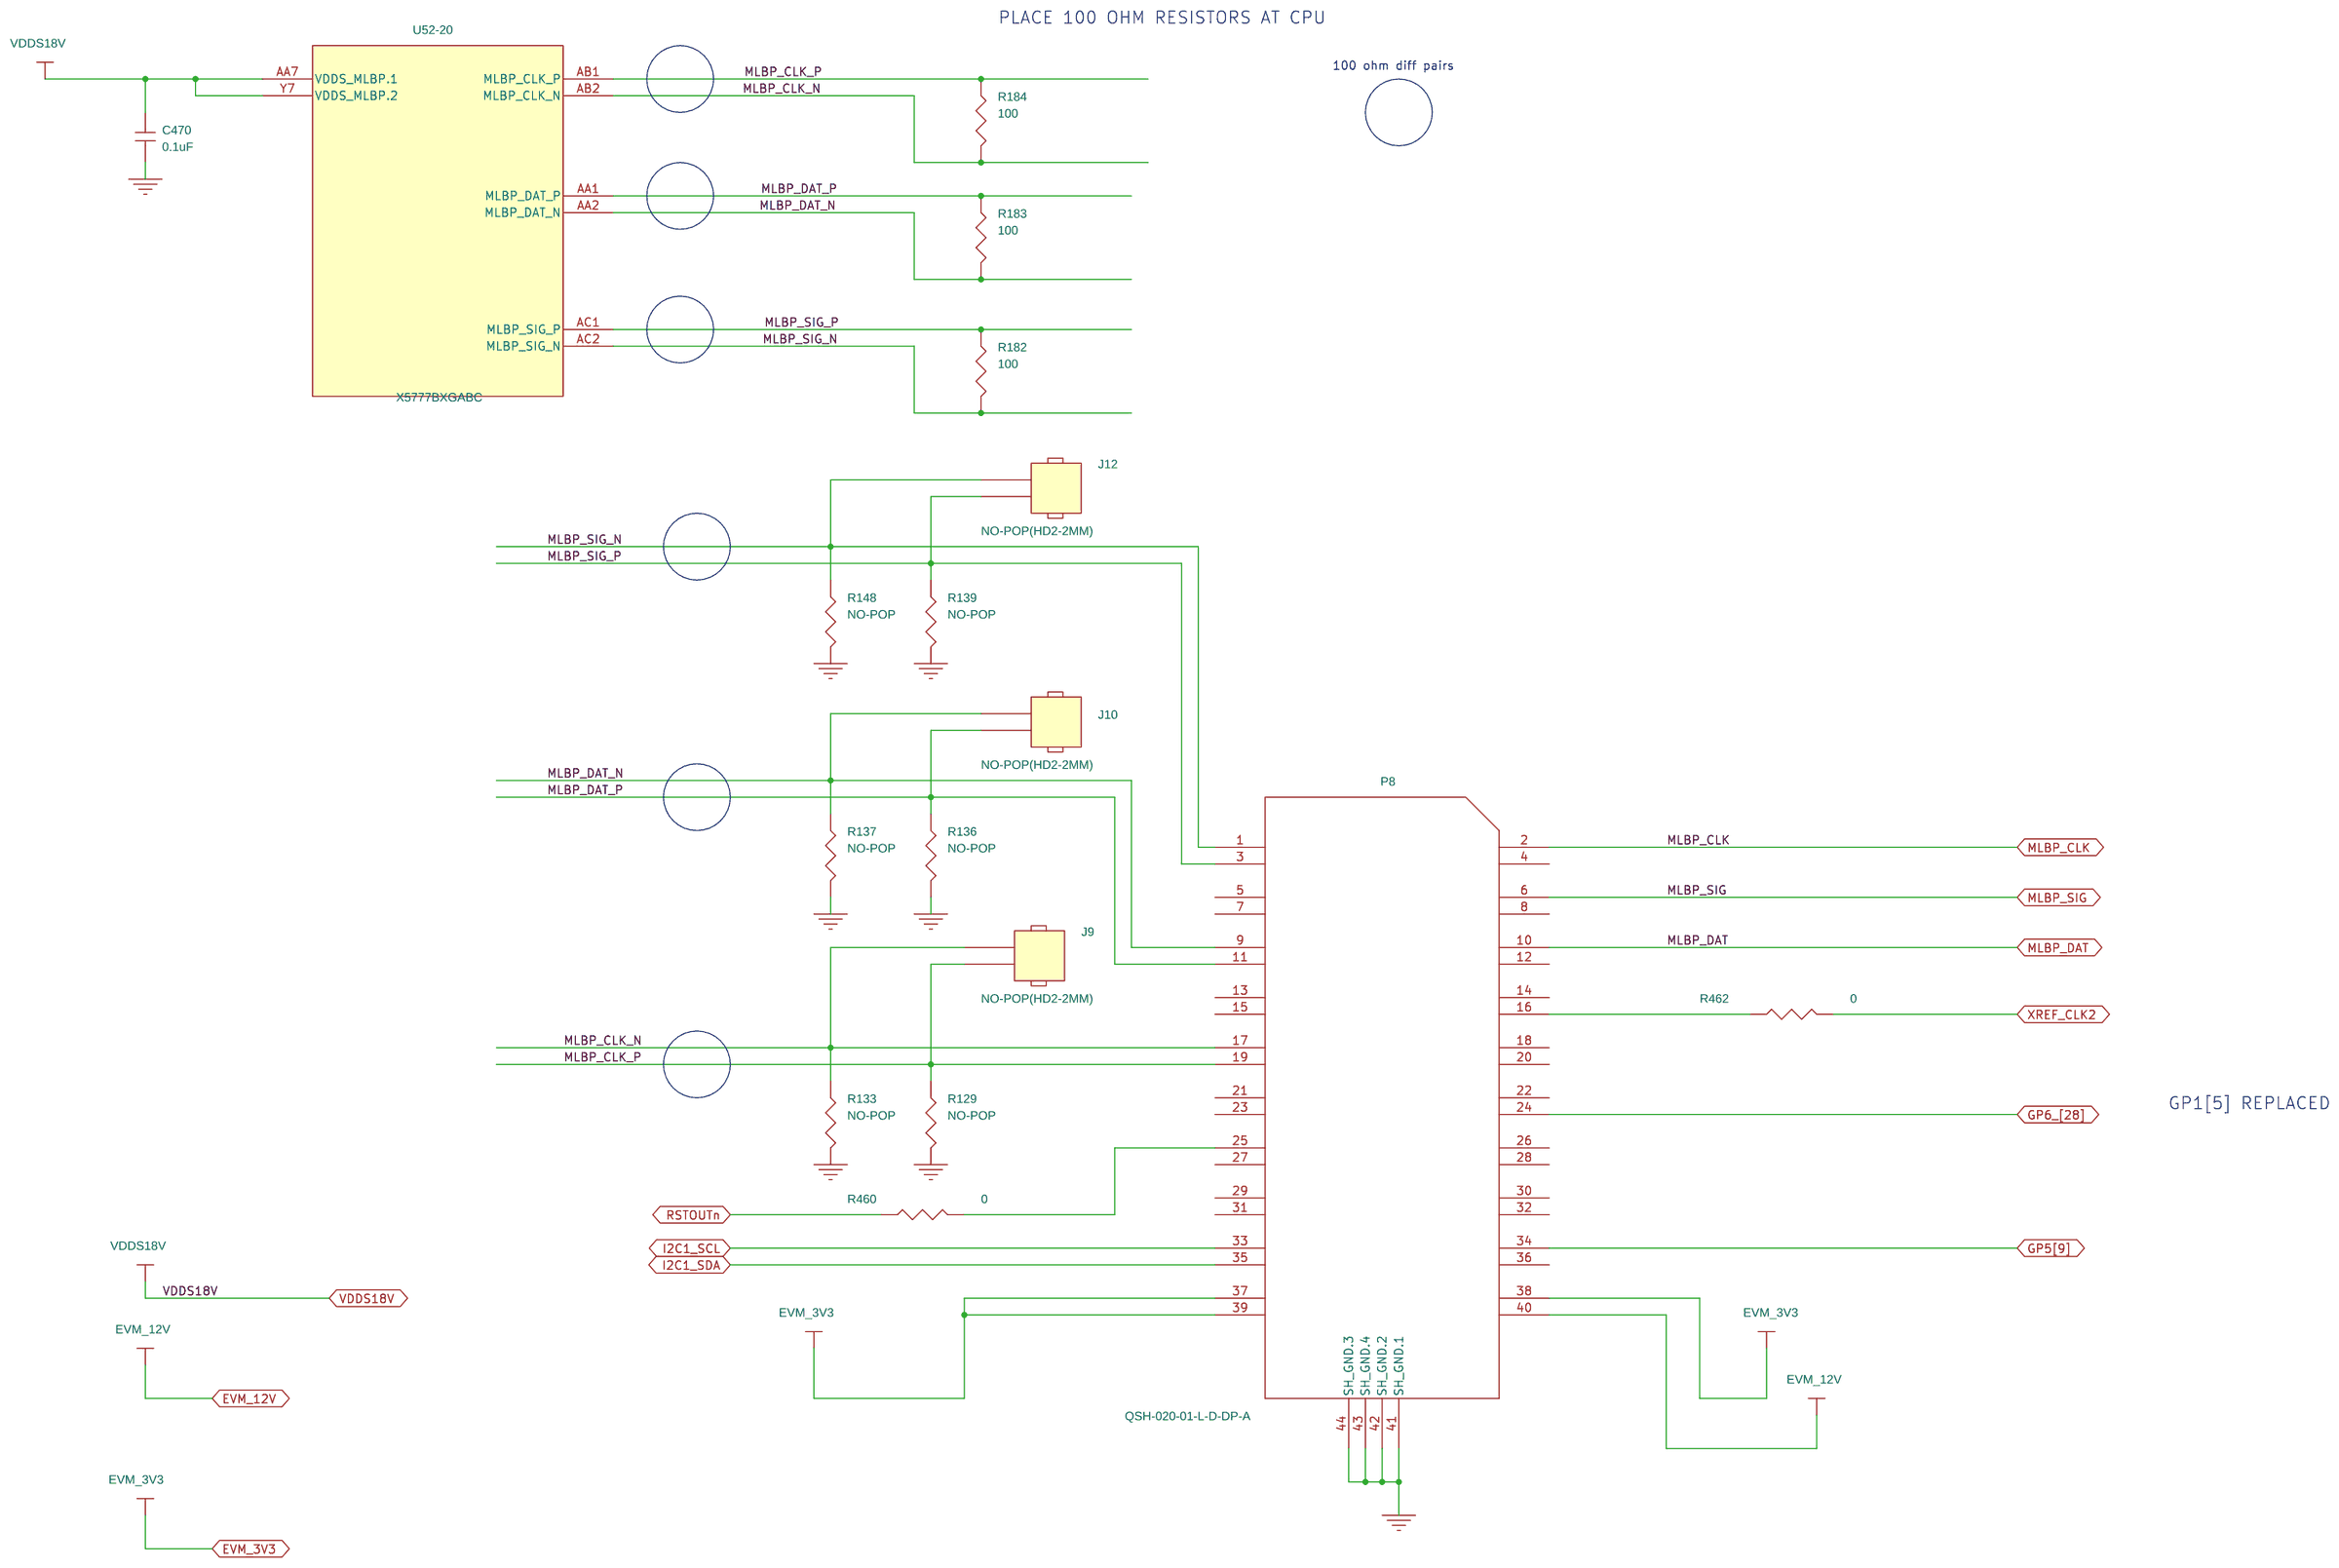
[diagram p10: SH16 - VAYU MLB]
12 SH17 - VAYU ETHERNET: size B; rev: A
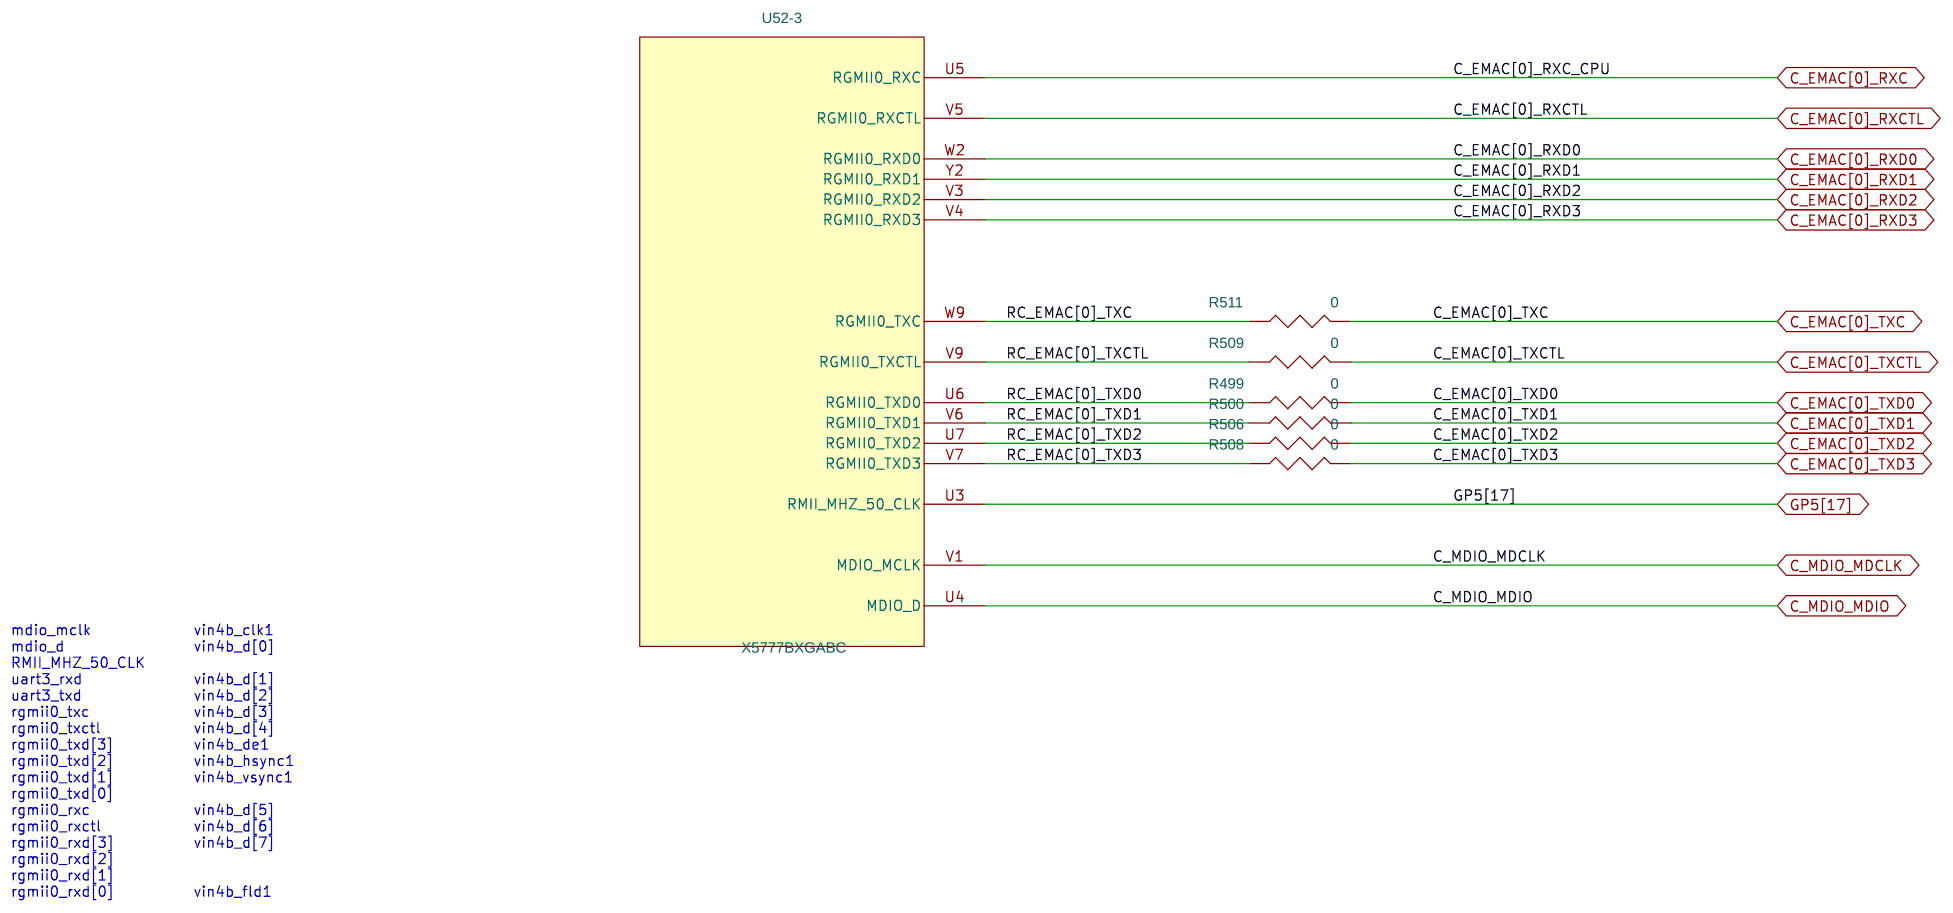
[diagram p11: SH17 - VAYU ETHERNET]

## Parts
sheet SH02 - VAYU MCASP
R177  NO-POP  [r402-25]
R221  0  [r201-6p6spc]
R224  0  [r201-6p6spc]
R225  0  [r201-6p6spc]
R231  0  [r201-6p6spc]
R236  0  [r201-6p6spc]
R237  0  [r201-6p6spc]
R242  0  [r201-6p6spc]
R243  0  [r201-6p6spc]
R263  0  [r201-6p6spc]
R525  0  [r402-25]
R526  0  [r402-25]
R527  NO-POP  [r402-25]
R538  0  [r402-25]
R541  NO-POP  [r402-25]
R602  0  [r201-6p6spc]
R609  0  [r201-6p6spc]
R613  0  [r201-6p6spc]
R621  0  [r201-6p6spc]
R626  0  [r201-6p6spc]
R667  NO-POP  [r201-6p6spc]
R764  NO-POP  [r201-6p6spc]
TP53  TestPoint1_0  [tp1-18rd8]
TP56  TestPoint1_0  [tp1-18rd8]
sheet SH06 - CAN CONNECTORS
C525  4700pF  [c402-25]
C527  .1uF  [c402-25]
C531  .1uF  [c402-25]
C540  .1uF  [c402-25]
JP1  NO-POP(HEADER 3)  [JUMP1X3-6040]
JP2  HEADER 2  [JUMP1X2-6040]
JP3  HEADER 2  [JUMP1X2-6040]
R238  62  [r1206-40x70]
R255  62  [r1206-40x70]
R615  10K  [r402-25]
R617  NO-POP  [r402-25]
R628  NO-POP  [r402-25]
R645  NO-POP  [r402-25]
R646  0  [r402-25]
U54  SN65HVDA541  [so8-25x75]
U110  SN74LVC1G04DCK  [dck-5]
sheet SH07 - SPI FLASH
C67  0.1uF  [c402-25]
C293  0.1uF  [c402-25]
R128  10K  [r402-25]
R130  NO-POP  [r402-25]
R131  10K  [r402-25]
R132  NO-POP  [r402-25]
R442  10K  [r402-25]
R443  NO-POP  [r402-25]
R444  NO-POP  [r402-25]
R465  10  [r402-25]
R468  NO-POP  [r402-25]
R726  0  [r402-25]
R727  10  [r402-25]
R728  10  [r402-25]
R729  0  [r402-25]
R730  0  [r402-25]
R731  0  [r402-25]
R732  NO-POP  [r402-25]
R733  0  [r402-25]
U18  S25FL256SAGMFV001  [so16-25x75-300]
sheet SH09 - NAND FLASH
C24  .1uF  [c402-25]
C29  0.01uF  [c402-25]
C30  0.01uF  [c402-25]
C35  0.01uF  [c402-25]
R37  0  [r402-25]
R38  10K  [r402-25]
R56  10K  [r402-25]
RU4  74CBTLV1G125CRG4  [dck-5]
U6  MT29F2G16AADWP:D  [tsop48-10x60-micron]
sheet SH11 - NOR FLASH
C23  .1uF  [c402-25]
C241  .1uF  [c402-25]
C251  .1uF  [c402-25]
R46  10K  [r402-25]
R364  10K  [r402-25]
R370  10K  [r201-6p6spc]
R375  10K  [r201-6p6spc]
R376  10K  [r402-25]
R377  NO-POP  [r402-25]
R379  10K  [r402-25]
R381  10K  [r201-6p6spc]
R385  10K  [r402-25]
R388  10K  [r201-6p6spc]
R390  10K  [r201-6p6spc]
R391  10K  [r402-25]
R392  NO-POP  [r402-25]
R394  10K  [r201-6p6spc]
R395  10K  [r201-6p6spc]
R396  10K  [r201-6p6spc]
R397  10K  [r201-6p6spc]
R398  10K  [r201-6p6spc]
R400  10K  [r201-6p6spc]
R401  10K  [r201-6p6spc]
R402  10K  [r201-6p6spc]
R403  10K  [r201-6p6spc]
RU82  74CBTLV1G125CRG4  [dck-5]
U83  S29GL512S10TFI010  [tsop56-12x75]
sheet SH12 - eMMC MEMORY
C269  0.1uF  [c402-25]
C273  4.7uF  [c402-25]
C274  0.22uF  [c402-25]
C280  2.2uF  [c402-25]
C290  0.22uF  [c402-25]
C698  2.2uF  [c402-25]
C703  .1uF  [c402-25]
R404  47K  [r402-25]
R405  47K  [r402-25]
R406  47K  [r402-25]
R407  0  [r402-25]
R410  47K  [r402-25]
R414  47K  [r402-25]
R417  47K  [r402-25]
R422  47K  [r402-25]
R423  47K  [r402-25]
R426  47K  [r402-25]
R427  0  [r402-25]
R428  47K  [r402-25]
R429  0  [r402-25]
R433  NO-POP  [r402-25]
R798  NP  [r402-25]
U14  MTFC8GLWDM-3M AIT Z  [fbga153-169-p5-combo]
U143  SN74LVC1G125DCKR  [dck-5]
sheet SH13 - I2C EXPANDER
C543  .1uF  [c402-25]
C544  .1uF  [c402-25]
C691  .1uF  [c402-25]
C697  .1uF  [c402-25]
DS1  LED_GRN  [led1206-59x59]
DS2  LED_GRN  [led1206-59x59]
DS3  LED_GRN  [led1206-59x59]
DS4  LED_GRN  [led1206-59x59]
R638  0  [r402-25]
R639  NO-POP  [r402-25]
R640  NO-POP  [r402-25]
R647  10K  [r402-25]
R648  10K  [r402-25]
R649  10K  [r402-25]
R655  10K  [r402-25]
R656  10K  [r402-25]
R660  10K  [r402-25]
R661  NO-POP  [r402-25]
R662  NO-POP  [r402-25]
R663  NO-POP  [r402-25]
R665  NO-POP  [r402-25]
R666  10K  [r402-25]
R674  330  [r402-25]
R676  330  [r402-25]
R677  330  [r402-25]
R682  330  [r402-25]
R749  NO-POP  [r402-25]
R750  10K  [r402-25]
R751  NO-POP  [r402-25]
R752  10K  [r402-25]
R753  10K  [r402-25]
R754  NO-POP  [r402-25]
R785  NOPOP  [r402-25]
R786  0  [r402-25]
R789  10K  [r402-25]
R790  10K  [r402-25]
R791  10K  [r402-25]
R792  10K  [r402-25]
R793  100  [r402-25]
R794  100  [r402-25]
U57  PCF8575  [pw24-14x70]
U58  PCF8575  [pw24-14x70]
U119  PCF8575  [pw24-14x70]
U139  SN74LVC1G125DCKR  [dck-5]
U140  SN74LVC1G125DCKR  [dck-5]
sheet SH15 - SD CARD
C12  0.1uF  [c402-25]
C14  0.1uF  [c402-25]
C15  0.1uF  [c402-25]
C16  0.1uF  [c402-25]
C233  10uF  [c603-35x45]
C693  0.1uF  [c402-25]
C694  10uF  [c603-35x45]
C695  NO-POP  [c603-35x45]
P14  MicroSD_CARD  [molex-49225-201]
R14  47K  [r402-25]
R15  47K  [r402-25]
R16  47K  [r402-25]
R17  10K  [r402-25]
R18  47K  [r402-25]
R19  47K  [r402-25]
R304  1K  [r402-25]
R327  10K  [r402-25]
R340  33  [r402-25]
R341  33  [r402-25]
R342  33  [r402-25]
R343  33  [r402-25]
R344  33  [r402-25]
R345  33  [r402-25]
R772  10K  [r603-35x45]
R774  0  [r603-35x45]
R787  NO-POP  [r402-25]
R823  NP  [r402-25]
U77  TPD2E001DRL-Q1  [drl5-12x40]
U78  TPD2E001DRL-Q1  [drl5-12x40]
U79  TPD2E001DRL-Q1  [drl5-12x40]
U122  TPD2E001DRL-Q1  [drl5-12x40]
U123  TPS22965DSG  [dsg8-11x20]
sheet SH16 - VAYU MLB
C470  0.1uF  [c201-6p6spc]
J9  NO-POP(HD2-2MM)  [jump1x2-5635-2mm]
J10  NO-POP(HD2-2MM)  [jump1x2-5635-2mm]
J12  NO-POP(HD2-2MM)  [jump1x2-5635-2mm]
P8  QSH-020-01-L-D-DP-A  [qsh-020-dp-A]
R129  NO-POP  [r201-6p6spc]
R133  NO-POP  [r201-6p6spc]
R136  NO-POP  [r201-6p6spc]
R137  NO-POP  [r201-6p6spc]
R139  NO-POP  [r201-6p6spc]
R148  NO-POP  [r201-6p6spc]
R182  100  [r402-25]
R183  100  [r402-25]
R184  100  [r402-25]
R460  0  [r201-6p6spc]
R462  0  [r402-25]
sheet SH17 - VAYU ETHERNET
R499  0  [r201-6p6spc]
R500  0  [r201-6p6spc]
R506  0  [r201-6p6spc]
R508  0  [r201-6p6spc]
R509  0  [r201-6p6spc]
R511  0  [r201-6p6spc]
sheet SH28 - VAYU VOUT1 PORT LCD
U52  X5777BXGABC  [sktbga-zkk-6334-p760]  (sections -1,-10,-11,-12,-13,-14,-15,-16,-17,-18,-19,-2,-20,-21,-22,-23,-3,-4,-5,-6,-7,-8,-9)

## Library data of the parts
R130 R132 R177 R377 R392 R443 R444 R468 R527 R541 R617 R628 R639 R640 R645 R661-R663 R665 R732 R749 R751 R754 R823 = R: Part #: R0402-NOPOP
R221 R224 R225 R231 R236 R237 R242 R243 R263 R460 R602 R609 R613 R621 R626 = R: Part #: 103158-0001R
R37 R407 R429 R462 R525 R526 R538 R638 R646 R726 R729-R731 R733 R786 = R: Part #: 101370-0001R
R129 R133 R136 R137 R139 R148 R667 = R: Part #: R0201-NOPOP
R764 = R: Part #: r0201-nopop
TP53 TP56 = TestPoint1_0: Part #: TP-18RD8-NO-POP
C525 = CAP: Part #: 103217-1472R
C527 C531 C540 = CAP: Part #: 101587-1100R
JP1 = HEADER_3: Part #: NO-POP
JP2 JP3 = HEADER_2: Part #: 100115-0002R
R238 R255 = R: Part #: 100155-6200R
R38 R46 R56 R364 R376 R379 R385 R391 R615 R647-R649 R655 R656 R660 R666 R750 R752 R753 R789-R792 = R: Part #: 101370-1003R
U54 = SN65HVDA541: Part #: 103628-0001R
U110 = SN74LVC1GU04_1: Part #: 101057-0004R
C67 C293 C543 C544 C691 C697 C703 = CAP_NP: Part #: 101587-1100R
R17 R128 R131 R327 R442 = RESISTOR: Part #: 101370-1003R
R465 R727 R728 = R: Part #: 101370-1000R
U18 = SPI_EEPROM_1: Part #: 104273-0001R
C24 C241 = CAP_NP_2: Part #: 101587-1100R
C29 C30 C35 = CAPACITOR_NON-POL: Part #: 101587-1101R
RU4 RU82 = SN74LVC1G125: Part #: 101689-0125R
U6 = U-NAND-Micron_16bit_Socket_0: Part #: 103066-0002R
C23 C251 = CAP_.1_uF_10%_0603: Part #: 101587-1100R
R370 R375 R381 R388 R390 R394-R398 R400-R403 = R: Part #: 103158-1003R
U83 = AM29LV256M_0: Part #: 104225-0100R
C12 C14-C16 C269 C693 = Cap_100nF_Cermc_16V_10%_603_4: Part #: 101587-1100R
C273 = CAP: Part #: 103649-0470R
C274 C290 = Cap_100nF_Cermc_16V_10%_603_4: Part #: 101587-1220R
C280 C698 = CAP: Part #: 103649-0220R
R14-R16 R18 R19 R404-R406 R410 R414 R422 R423 R426 R428 = RESISTOR: Part #: 101370-4703R
R417 = R: Part #: 102145-4703R
R427 = RESISTOR: Part #: 101370-0001R
R433 R787 = RESISTOR: Part #: R0402-NOPOP
R785 R798 = R: Part #: r0402-nopop
U14 = MTFC16GJVEC-4M-169WFBGA: Part #: 104412-0008R
U139 U140 U143 = SN74LVC1G125: Part #: 101057-0125R
DS1-DS3 = LED_0: Part #: 100823-0001R
DS4 = LED_RED_0: Part #: 100823-0001R
R674 R676 R677 R682 = R_0: Part #: 101370-3301R
R793 R794 = R_0: Part #: 101370-1001R
U57 U58 U119 = PCF8575_1: Part #: 102385-0001R
C233 C694 = CAP: Part #: 102963-0101R
C695 = CAP: Part #: C0603-NOPOP
P14 = MM_CARD_0: Part #: 103053-0001R
R304 = RESISTOR: Part #: 101370-1002R
R340-R345 = RESISTOR: Part #: 101370-3300R
R772 = RESISTOR: Part #: 100687-1003R
R774 = R: Part #: 100687-0001R
U77-U79 U122 = TPDE0001RSE_0: Part #: 102728-0001R
U123 = TPS22965DSG: Part #: 104267-0001R
C470 = CAP_NP: Part #: 103241-1100R
J9 J10 J12 = HEADER_2: Part #: NO-POP
P8 = QSH-020-01-L-D-DP-A: Part #: 103429-0020R
R182-R184 = R: Part #: 101370-1001R
R499 R500 R506 R508 R509 R511 = R0402-22: Part #: 103158-0001R
U52 = VAYU_DEC_3_2: Part #: 104183-0003R

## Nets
GND: C12.2 C14.2 C15.2 C16.2 C23.2 C24.2 C29.2 C30.2 C35.2 C67.2 C233.2 C241.2 C251.2 C269.2 C273.2 C274.2 C280.2 C290.2 C293.2 C470.2 C525.2 C527.2 C531.2 C540.2 C543.1 C544.1 C691.1 C693.2 C694.2 C695.2 C697.1 C698.2 C703.1 JP1.2 P8.41(SH_GND.1) P8.42(SH_GND.2) P8.43(SH_GND.4) P8.44(SH_GND.3) P14.6(VSS) R129.2 R133.2 R136.2 R137.2 R139.2 R148.2 R304.2 R370.1 R375.1 R377.2 R381.1 R388.1 R390.1 R392.2 R394.1 R395.1 R396.1 R397.1 R398.1 R400.1 R401.1 R402.1 R403.1 R615.2 R617.2 R648.2 R649.2 R655.2 R656.2 R660.2 R661.2 R749.2 R751.2 R752.2 RU4.3(GND) RU82.3(GND) U6.13(GND1) U6.25(GND2) U6.36(GND3) U6.48(GND4) U14.C4(VSS.1) U14.E7(VSS.2) U14.G5(VSS.3) U14.H10(VSS.4) U14.K8(VSS.5) U14.N2(VSS.6) U14.N5(VSS.7) U14.P4(VSS.8) U14.P6(VSS.9) U18.10(VSS) U54.2(GND) U57.12(GND) U58.12(GND) U77.4(GND) U78.4(GND) U79.4(GND) U83.33(VSS1) U83.52(VSS2) U110.3(GND) U119.12(GND) U122.4(GND) U123.5(GND) U123.9(PWR_PAD) U139.3(GND) U140.3(GND) U143.2(I) U143.3(GND) ; also on sheet 13 15 16 17 18 19 20 21 24 25 26 27 28 29 30 31 32 33 34 35 36 37 38 39 40 42 43 46 47 49 50 51 52 53 54 55 56 57 58 60 61 62 63 64 65 66 67 68 69 70 71 72 73 74 75 77 79 80 81 84 85 86 87 88 89
VDDS18V: C470.1 U52.AA7(VDDS_MLBP.1) U52.Y7(VDDS_MLBP.2) ; also on sheet 35 36 66 74
VDDSHV5: R646.1 ; also on sheet 33 76 79
VIN2_S0: U119.6(P2) ; also on sheet 25
VIN6_SEL_S0: U119.5(P1) ; also on sheet 86
VIN[5]A_D[8]: R525.2 ; also on sheet 60
VIN[5]A_D[9]: R526.2 ; also on sheet 60
VIN[5]A_D[10]: U52.AB9(MCSAP5_FSX) ; also on sheet 60
VIN[5]A_D[11]: R538.2 ; also on sheet 60
VIN[5]A_D[12]: U52.D17(MCASP4_AXR1) ; also on sheet 60
VIN[5]A_D[13]: U52.G16(MCASP4_AXR0) ; also on sheet 60
VIN[5]A_D[14]: U52.A21(MCASP4_FSX) ; also on sheet 60
VIN[5]A_D[15]: U52.C18(MCASP4_ACLKX) ; also on sheet 60
AIC3106_MCLK: R263.2 ; also on sheet 55
AQSPI1_CS[0]: R731.1 ; also on sheet 14
AQSPI1_D[0]: R729.1 ; also on sheet 14
AQSPI1_D[1]: R730.2 ; also on sheet 14
AQSPI1_D[2]: R733.2 ; also on sheet 14
AQSPI1_D[3]: R726.1 ; also on sheet 14
AQSPI1_RTCLK: R727.2 ; also on sheet 14
AQSPI1_SCLK: R727.1 R728.2 ; also on sheet 14
B_QSPI1_SCLK: R465.1 R468.2 ; also on sheet 17
C_EMAC[0]_RXC: U52.U5(RGMII0_RXC) ; also on sheet 85
C_EMAC[0]_RXCTL: U52.V5(RGMII0_RXCTL) ; also on sheet 85
C_EMAC[0]_RXD0: U52.W2(RGMII0_RXD0) ; also on sheet 85
C_EMAC[0]_RXD1: U52.Y2(RGMII0_RXD1) ; also on sheet 85
C_EMAC[0]_RXD2: U52.V3(RGMII0_RXD2) ; also on sheet 85
C_EMAC[0]_RXD3: U52.V4(RGMII0_RXD3) ; also on sheet 85
C_EMAC[0]_TXC: R511.2 ; also on sheet 85
C_EMAC[0]_TXCTL: R509.2 ; also on sheet 85
C_EMAC[0]_TXD0: R499.2 ; also on sheet 85
C_EMAC[0]_TXD1: R500.2 ; also on sheet 85
C_EMAC[0]_TXD2: R506.2 ; also on sheet 85
C_EMAC[0]_TXD3: R508.2 ; also on sheet 85
C_MCA1_ACLKX: R602.1 ; also on sheet 86
C_MCA1_AFSX: R609.1 ; also on sheet 86
C_MCA1_AXR0: U52.G12(MCASP1_AXR0) ; also on sheet 86
C_MCA1_AXR1: U52.F12(MCASP1_AXR1) ; also on sheet 86
C_MCA2_ACLKX: R242.1 ; also on sheet 86
C_MCA2_AFSX: R236.2 ; also on sheet 86
C_MCA2_AXR0: U52.B15(MCASP2_AXR0) ; also on sheet 86
C_MCA2_AXR1: U52.A15(MCASP2_AXR1) ; also on sheet 86
C_MCA2_AXR2: U52.C15(MCASP2_AXR2) ; also on sheet 86
C_MCA2_AXR3: U52.A16(MCASP2_AXR3) ; also on sheet 86
C_MCA2_AXR4: U52.D15(MCASP2_AXR4) ; also on sheet 86
C_MCA2_AXR5: U52.B16(MCASP2_AXR5) ; also on sheet 86
C_MCA2_AXR6: U52.B17(MCASP2_AXR6) ; also on sheet 86
C_MCA2_AXR7: U52.A17(MCASP2_AXR7) ; also on sheet 86
C_MCA3_ACLKX: R237.1 ; also on sheet 86
C_MCA3_AFSX: R224.2 ; also on sheet 86
C_MCA3_AXR0: R243.2 ; also on sheet 86
C_MCA3_AXR1: R621.2 ; also on sheet 86
C_MCA6_AXR0: U52.B12(MCASP1_AXR8) ; also on sheet 86
C_MCA6_AXR1: U52.A11(MCASP1_AXR9) ; also on sheet 86
C_MCA6_CLKX: R225.1 ; also on sheet 86
C_MCA6_FSX: R221.1 ; also on sheet 86
C_MCA7_AXR0: U52.E14(MCASP1_AXR12) ; also on sheet 86
C_MCA7_AXR1: U52.A13(MCASP1_AXR13) ; also on sheet 86
C_MCA7_CLKX: R613.1 ; also on sheet 86
C_MCA7_FSX: R231.1 ; also on sheet 86
C_MDIO_MDCLK: U52.V1(MDIO_MCLK) ; also on sheet 85
C_MDIO_MDIO: U52.U4(MDIO_D) ; also on sheet 85
C_XREF_CLK1: R626.2 ; also on sheet 86
CAM_FPD_MUX_S0: U119.7(P3) ; also on sheet 24
CAN_PHY_3V3: C527.1 C540.1 R645.2 R646.2 U54.5(VIO/NC) U110.5(VCC)
CON_LCD_PWR_DN: U58.18(P15) ; also on sheet 26
CON_MMC1_CLK: P14.5(CLK) R17.2 R343.2 U78.3(IO1)
CON_MMC1_CMD: P14.3(CMD) R16.2 R344.2 U78.5(IO2)
CON_MMC1_DAT0: P14.7(DAT0) R18.2 R342.2 U77.5(IO2)
CON_MMC1_DAT1: P14.8(DAT1) R19.2 R341.2 U77.3(IO1)
CON_MMC1_DAT2: P14.1(DAT2) R14.2 R340.2 U79.5(IO2)
CON_MMC1_DAT3: P14.2(DAT3) R15.2 R345.2 U79.3(IO1)
DCAN1_RX: JP2.2 U54.4(RXD) ; also on sheet 87
DCAN1_TX: JP2.1 R617.1 U54.1(TXD) ; also on sheet 87
DCAN2_RX: JP3.2 ; also on sheet 84
DCAN2_TX: JP3.1 ; also on sheet 84
EVM_1V8: R407.2 R787.1 ; also on sheet 26 52 53 61 69 74
EVM_3V3: C23.1 C24.1 C29.1 C30.1 C35.1 C67.1 C241.1 C251.1 C293.1 C543.2 C544.2 C691.2 C694.1 C697.2 C703.2 P8.37 P8.38 P8.39 R38.2 R46.2 R56.2 R128.1 R131.2 R364.2 R376.1 R379.1 R385.2 R391.1 R429.2 R442.1 R639.1 R640.1 R645.1 R647.1 R662.1 R663.1 R665.1 R666.1 R674.1 R676.1 R677.1 R682.1 R750.1 R753.1 R754.1 R772.1 R789.1 R790.1 R791.1 R792.1 R798.2 RU4.5(VCC) RU82.5(VCC) U6.12(VCC) U6.34(VCC2) U6.37(VCC3) U6.39(VCC4) U18.2(VCC) U18.14(VIO/RFU) U57.24(VDD) U58.24(VDD) U83.29(VIO) U83.43(VCC) U119.24(VDD) U123.1(VIN.1) U123.2(VIN.2) U139.5(VCC) U140.5(VCC) U143.5(VCC) ; also on sheet 14 15 16 17 18 24 25 26 27 28 29 30 31 32 33 49 50 51 52 53 56 57 58 60 61 69 70 78 84 85 86 87 88
EVM_3V3_SD: C12.1 C14.1 C15.1 C16.1 C233.1 P14.4(VDD) R823.1 U77.1(VCC) U78.1(VCC) U79.1(VCC) U123.7(VOUT.2) U123.8(VOUT.1)
EVM_5V0: C531.1 R628.1 U54.3(VCC) ; also on sheet 26 27 29 31 49 54 61 78
EVM_12V: P8.40 ; also on sheet 31 61 67 80
EXP_ETH0_RSTn: U58.13(P10) ; also on sheet 56
EXP_ETH1_RSTn: U58.14(P11) ; also on sheet 57
FLASH_BYTE: R391.2 R392.1 U83.53(~{BYT}E)
FLASH_WP: R377.1 R379.2 U83.16(~{WP}/ACC)
FORCE_EMU: U57.20(P17) ; also on sheet 18
GP5[0]: U52.B14(MCASP1_ACLKR) ; also on sheet 61
GP5[1]: U52.J14(MCASP1_FSR) ; also on sheet 61
GP5[4]: U52.G13(MCASP1_AXR2) ; also on sheet 52
GP5[5]: U52.J11(MCASP1_AXR3) ; also on sheet 52
GP5[6]: U52.E12(MCASP1_AXR4) ; also on sheet 52
GP5[7]: U52.F13(MCASP1_AXR5) ; also on sheet 52
GP5[8]: U52.C12(MCASP1_AXR6) ; also on sheet 52
GP5[9]: P8.34 U52.D12(MCASP1_AXR7)
GP5[17]: U52.U3(RMII_MHZ_50_CLK) ; also on sheet 61
GP6[17]: U52.D18(XREF_CLK0) ; also on sheet 60
GP6[20]: U52.C23(XREF_CLK3) ; also on sheet 62
GP6_[28]: P8.24 ; also on sheet 83
GPMC_A1: U83.31(A0) ; also on sheet 15
GPMC_A2: U83.26(A1) ; also on sheet 15
GPMC_A3: U83.25(A2) ; also on sheet 15
GPMC_A4: U83.24(A3) ; also on sheet 15
GPMC_A5: U83.23(A4) ; also on sheet 15
GPMC_A6: U83.22(A5) ; also on sheet 15
GPMC_A7: U83.21(A6) ; also on sheet 15
GPMC_A8: U83.20(A7) ; also on sheet 16
GPMC_A9: U83.10(A8) ; also on sheet 16
GPMC_A10: U83.9(A9) ; also on sheet 16
GPMC_A11: U83.8(A10) ; also on sheet 16
GPMC_A12: U83.7(A11) ; also on sheet 16
GPMC_A13: R394.2 U83.6(A12) ; also on sheet 17
GPMC_A14: R396.2 U83.5(A13) ; also on sheet 17
GPMC_A15: R397.2 U83.4(A14) ; also on sheet 17
GPMC_A16: R400.2 U83.3(A15) ; also on sheet 17
GPMC_A17: R395.2 U83.54(A16) ; also on sheet 17
GPMC_A18: R370.2 U83.19(A17) ; also on sheet 17
GPMC_A19: R375.2 U83.18(A18) ; also on sheet 17
GPMC_A20: R390.2 U83.11(A19) ; also on sheet 17
GPMC_A21: R388.2 U83.12(A20) ; also on sheet 17
GPMC_A22: R381.2 U83.15(A21) ; also on sheet 17
GPMC_A23: R403.2 U83.2(A22) ; also on sheet 17
GPMC_A24: R402.2 U83.1(A23) ; also on sheet 17
GPMC_A25: R401.2 U83.56(A24) ; also on sheet 17
GPMC_A26: R398.2 U83.55(A25/NC4) ; also on sheet 17
GPMC_ADVn_ALE: U6.17(ALE) ; also on sheet 14
GPMC_BE0n_CLE: U6.16(CLE) ; also on sheet 14
GPMC_D00: U6.29(I/O0) U83.35(DQ0) ; also on sheet 15 18
GPMC_D01: U6.30(I/O1) U83.37(DQ1) ; also on sheet 15 18
GPMC_D02: U6.31(I/O2) U83.39(DQ2) ; also on sheet 15 18
GPMC_D03: U6.32(I/O3) U83.41(DQ3) ; also on sheet 15 18
GPMC_D04: U6.41(I/O4) U83.44(DQ4) ; also on sheet 15 18
GPMC_D05: U6.42(I/O5) U83.46(DQ5) ; also on sheet 15 18
GPMC_D06: U6.43(I/O6) U83.48(DQ6) ; also on sheet 15 18
GPMC_D07: U6.44(I/O7) U83.50(DQ7) ; also on sheet 15 18
GPMC_D08: U6.26(I/O8) U83.36(DQ8) ; also on sheet 15 18
GPMC_D09: U6.27(I/O9) U83.38(DQ9) ; also on sheet 15 18
GPMC_D10: U6.28(I/O10) U83.40(DQ10) ; also on sheet 15 18
GPMC_D11: U6.33(I/O11) U83.42(DQ11) ; also on sheet 15 18
GPMC_D12: U6.40(I/O12) U83.45(DQ12) ; also on sheet 15 18
GPMC_D13: U6.45(I/O13) U83.47(DQ13) ; also on sheet 15 18
GPMC_D14: U6.46(I/O14) U83.49(DQ14) ; also on sheet 15 18
GPMC_D15: U6.47(I/O15) U83.51(DQ15/A-1) ; also on sheet 15 18
GPMC_nCS0: RU4.2(I) RU82.2(I) ; also on sheet 14
GPMC_OEN_REN: R46.1 U6.8(\\~{R}E) U83.34(~{OE}) ; also on sheet 14
GPMC_WAIT: R37.1 ; also on sheet 14
GPMC_WEn: R385.1 U6.18(\\~{W}E) U83.13(~{WE}) ; also on sheet 14
GPMC_WPN: U6.19(\\~{W}P) ; also on sheet 18
HDMI_CT_HPD: U119.8(P4) ; also on sheet 27
HDMI_LS_OE: U119.9(P5) ; also on sheet 27
I2C1_SCL: P8.33 U57.22(SCL) U58.22(SCL) ; also on sheet 26 53 55 61 87 88
I2C1_SDA: P8.35 U57.23(SDA) U58.23(SDA) ; also on sheet 26 53 55 61 87 88
I2C2_SCL: U119.22(SCL) ; also on sheet 28 29 62 84
I2C2_SDA: U119.23(SDA) ; also on sheet 28 29 62 84
MCASP1_ENn: U57.18(P15) ; also on sheet 18 52
MLBP_CLK: P8.2 R541.2
MLBP_CLK_N: J9.1 P8.17 R133.1 R184.2 U52.AB2(MLBP_CLK_N)
MLBP_CLK_P: J9.2 P8.19 R129.1 R184.1 U52.AB1(MLBP_CLK_P)
MLBP_DAT: P8.10 R177.2
MLBP_DAT_N: J10.1 P8.9 R137.1 R183.2 U52.AA2(MLBP_DAT_N)
MLBP_DAT_P: J10.2 P8.11 R136.1 R183.1 U52.AA1(MLBP_DAT_P)
MLBP_SIG: P8.6 R527.2
MLBP_SIG_N: J12.1 P8.1 R148.1 R182.2 U52.AC2(MLBP_SIG_N)
MLBP_SIG_P: J12.2 P8.3 R139.1 R182.1 U52.AC1(MLBP_SIG_P)
MMC1_3V3: R14.1 R15.1 R16.1 R17.1 R18.1 R19.1 R327.1 ; also on sheet 78
MMC1_CLK: R343.1 ; also on sheet 83
MMC1_CMD: R344.1 ; also on sheet 83
MMC1_DAT0: R342.1 ; also on sheet 83
MMC1_DAT1: R341.1 ; also on sheet 83
MMC1_DAT2: R340.1 ; also on sheet 83
MMC1_DAT3: R345.1 ; also on sheet 83
MMC1_SD_CD: P14.9(INSERT) R327.2 R787.2 U122.5(IO2) ; also on sheet 83
MMC2_BOOT_OVR: R791.2 U119.18(P15) U140.2(I)
MMC2_BOOT_OVR_OEN: R792.2 U119.17(P14) U140.1(OE)
MMC2_BOOTn: R794.2 U57.15(P12) ; also on sheet 17 18 35
MMC2_CLK: R427.1 R433.2 ; also on sheet 17
MMC2_CMD: R410.2 U14.M5(CMD) ; also on sheet 17
MMC2_DAT0: R404.2 U14.A3(DAT0) ; also on sheet 17
MMC2_DAT1: R422.2 U14.A4(DAT1) ; also on sheet 17
MMC2_DAT2: R426.2 U14.A5(DAT2) ; also on sheet 17
MMC2_DAT3: R406.2 U14.B2(DAT3) ; also on sheet 17
MMC2_DAT4: R405.2 U14.B3(DAT4) ; also on sheet 17
MMC2_DAT5: R414.2 U14.B4(DAT5) ; also on sheet 17
MMC2_DAT6: R423.2 U14.B5(DAT6) ; also on sheet 17
MMC2_DAT7: R428.2 U14.B6(DAT7) ; also on sheet 17
MMC2_VCCQ: C274.1 C280.1 R404.1 R405.1 R406.1 R407.1 R410.1 R414.1 R417.2 R422.1 R423.1 R426.1 R428.1 R433.1 R798.1 U14.C6(VDD.1) U14.M4(VDD.2) U14.N4(VDD.3) U14.P3(VDD.4) U14.P5(VDD.5)
MMC2_VDDI: C269.1 C698.1 U14.C2(VDDI.1)
MMC2_VFF: C273.1 C290.1 R429.1 U14.E6(VFF.1) U14.F5(VFF.2) U14.J10(VFF.3) U14.K9(VFF.4)
MMC_PWR_ON: R772.2 U57.9(P5) U123.3(ON)
NAND_BOOTn: RU4.1(OE) U57.13(P10) ; also on sheet 18
NOR_BOOTn: R793.2 RU82.1(OE) U57.14(P11) ; also on sheet 18
NOR_BOOTn_OVR: R789.2 U119.20(P17) U139.2(I)
NOR_BOOTn_OVR_OEN: R790.2 U119.19(P16) U139.1(OE)
NOR_CEn: R364.1 RU82.4(O) U83.32(~{CE})
PCF8575_INT: R638.1 R647.2 R785.1 R786.1 ; also on sheet 87
PCI_SW_RESETn: U58.17(P14) ; also on sheet 31
PMIC_OFF: U110.2(I) ; also on sheet 33 63
PS_EVM_5V0: R774.1 ; also on sheet 64 67 68 69 73 78
QSPI1_CS[0]: R732.1 ; also on sheet 17
QSPI1_D[0]: R444.1 ; also on sheet 17
QSPI1_D[1]: R132.2 ; also on sheet 17
QSPI1_D[2]: R443.2 ; also on sheet 17
QSPI1_D[3]: R130.1 ; also on sheet 17
QSPI1_RTCLK: R465.2 ; also on sheet 17
QSPI_BOOT: U57.16(P13) ; also on sheet 17 18
R_QSPI1_CS[0]: R131.1 R731.2 R732.2 U18.7(~{CS})
R_QSPI1_D[0]: R444.2 R729.2 U18.15(SI/IO0)
R_QSPI1_D[1]: R132.1 R730.1 U18.8(SO/IO1)
R_QSPI1_D[2]: R442.2 R443.1 R733.1 U18.9(~{WP}/IO2)
R_QSPI1_D[3]: R128.2 R130.2 R726.2 U18.1(~{HOLD}/IO3)
R_QSPI1_SCLK: R468.1 R728.1 U18.16(SCLK)
RC_EMAC[0]_TXC: R511.1 U52.W9(RGMII0_TXC)
RC_EMAC[0]_TXCTL: R509.1 U52.V9(RGMII0_TXCTL)
RC_EMAC[0]_TXD0: R499.1 U52.U6(RGMII0_TXD0)
RC_EMAC[0]_TXD1: R500.1 U52.V6(RGMII0_TXD1)
RC_EMAC[0]_TXD2: R506.1 U52.U7(RGMII0_TXD2)
RC_EMAC[0]_TXD3: R508.1 U52.V7(RGMII0_TXD3)
RC_MCA1_ACLKX: R602.2 U52.C14(MCASP1_ACLKX)
RC_MCA1_AFSX: R609.2 U52.D14(MCASP1_FSX)
RC_MCA2_ACLKX: R242.2 U52.A19(MCASP2_ACLKX)
RC_MCA2_AFSX: R236.1 U52.A18(MCASP2_FSX)
RC_MCA3_ACLKX: R237.2 U52.B18(MCASP3_ACLKX)
RC_MCA3_AFSX: R224.1 U52.F15(MCASP3_FSX)
RC_MCA3_AXR0: R243.1 U52.B19(MCASP3_AXR0)
RC_MCA3_AXR1: R621.1 U52.C17(MCASP3_AXR1)
RC_MCA6_CLKX: R225.2 U52.B13(MCASP1_AXR10)
RC_MCA6_FSX: R221.2 U52.A12(MCASP1_AXR11)
RC_MCA7_CLKX: R613.2 U52.G14(MCASP1_AXR14)
RC_MCA7_FSX: R231.2 U52.F14(MCASP1_AXR15)
RC_VIN[5]A_D[8]: R177.1 R525.1 U52.AA4(MCASP5_AXR1)
RC_VIN[5]A_D[9]: R526.1 R527.1 U52.AB3(MCASP5_AXR0)
RC_VIN[5]A_D[11]: R538.1 R541.1 U52.AA3(MCASP5_ACLKX)
RC_XREF_CLK1: R626.1 U52.E17(XREF_CLK1)
RSTOUTn: R460.1 U18.3(~{RESET}/RFU) U83.14(~{RESET}) U143.1(OE) ; also on sheet 29 30 33 51 55 63
SEL_ENET_MUX_S0: U57.8(P4) ; also on sheet 85
SEL_GPMC_AD_VID_S0: U57.4(P0) ; also on sheet 15 16
SEL_HDMI_I2C2: TP53.1 U52.E15(MCASP2_ACLKR) ; also on sheet 84
SEL_I2C3_CAN2: U57.7(P3) ; also on sheet 84
SEL_UART3_SPI2: U57.19(P16) ; also on sheet 84
TMP102_ALERT: U58.20(P17) ; also on sheet 88
TS_LCD_GPIO1: U58.4(P0) ; also on sheet 26
TS_LCD_GPIO2: U58.5(P1) ; also on sheet 26
TS_LCD_GPIO3: U58.6(P2) ; also on sheet 26
TS_LCD_GPIO4: U58.7(P3) ; also on sheet 26
UART_SEL1_3: U57.17(P14) ; also on sheet 18 51
USB1_ID: U57.5(P1) ; also on sheet 50
USB1_VBUS_OCN: U58.15(P12) ; also on sheet 49
USB2_ID: U57.6(P2) ; also on sheet 50
USB2_VBUS: R764.1 ; also on sheet 49 50
USB2_VBUS_OCN: U58.16(P13) ; also on sheet 49
USER_LED1: DS1.1(cathode) U58.8(P4)
USER_LED2: DS2.1(cathode) U58.9(P5)
USER_LED3: DS3.1(cathode) U58.10(P6)
USER_LED4: DS4.1(cathode) U58.11(P7)
XREF_CLK2: R462.2 R667.2
N18472008: R752.1 R754.2 U119.21(A0)
N18472026: R749.1 R753.2 U119.3(A2)
N18472030: R750.2 R751.1 U119.2(A1)
N19012744: R615.1 R628.2 U54.8(STB) U110.4(O)
N19152868: P8.16 R462.1
N19152900: P8.25 R460.2
N19186343: R764.2 TP56.1 U52.A20(MCASP2_FSR)
N19635642: C693.1 R823.2 U122.1(VCC)
N19667111: R774.2 U123.4(VBIAS)
N19667155: C695.1 U123.6(CT)
N21264274: R786.2 U57.1(~{INT})
N21264312: R785.2 U119.1(~{INT})
N21632575: R794.1 U140.4(O)
N21632586: R793.1 U139.4(O)
N21763494: R638.2 U58.1(~{INT})
N21791561: R427.2 U14.M6(CLK)
N22632363: R263.1 R667.1 U52.B26(XREF_CLK2)
N23035792: DS2.2(ANODE) R676.2
N23035793: DS3.2(ANODE) R677.2
N23035794: DS4.2(ANODE) R682.2
N23035795: DS1.2(ANODE) R674.2
N23117477: R56.1 RU4.4(O) U6.9(\\~{CE})
N23117517: R37.2 R38.1 U6.7(R~{/B})
N23173932: R660.1 R665.2 U58.21(A0)
N23173950: R655.1 R662.2 U58.3(A2)
N23173954: R639.2 R648.1 U58.2(A1)
N23555533: R417.1 U14.K5(RSTN) U143.4(O)
N26498318: JP1.1 R238.1 U54.7(CANH)
N26498320: JP1.3 R255.2 U54.6(CANL)
N27808158: C525.1 R238.2 R255.1
N27834162: R376.2 U83.17(RY/~{BY})
N30225833: P14.10(INSERT_COM) R304.1
N33988069: R661.1 R666.2 U57.21(A0)
N33988087: R656.1 R663.2 U57.3(A2)
N33988091: R640.2 R649.1 U57.2(A1)

Not connected (* = marked no-connect by the designer): P8 4 5 7 8 12 13 14 15 18 20 21 22 23 26 27 28 29 30 31 32 36; P14 11 12 13 14 15; U6 1(NC-1)* 2(NC-2)* 3(NC-3)* 4(NC-4)* 5(NC-5)* 6(NC-6)* 10(NC-7)* 11(NC-8)* 14(NC-9)* 15(NC-10)* 20(NC-11)* 21(NC-12)* 22(NC-13)* 23(NC-14)* 24(NC-15)* 35(22-NC)* 38(23-NC)*; U14 A1(NC.A1) A2(NC.A2) A6(NC.A6) A7(NC.A7) A8(NC.A8) A9(NC.A9) A10(NC.A10) A11(NC.A11) A12(NC.A12) A13(NC.A13) A14(NC.A14) B1(NC.B1) B7(NC.B7) B8(NC.B8) B9(NC.B9) B10(NC.B10) B11(NC.B11) B12(NC.B12) B13(NC.B13) B14(NC.B14) C1(NC.C1) C3(NC.C3) C5(NC.C5) C7(NC.C7) C8(NC.C8) C9(NC.C9) C10(NC.C10) C11(NC.C11) C12(NC.C12) C13(NC.C13) C14(NC.C14) D1(NC.D1) D2(NC.D2) D3(NC.D3) D4(NC.D4) D12(NC.D12) D13(NC.D13) D14(NC.D14) E1(NC.E1) E2(NC.E2) E3(NC.E3) E5(NC.E5) E8(NC.E8) E9(NC.E9) E10(NC.E10) E12(NC.E12) E13(NC.E13) E14(NC.E14) F1(NC.F1) F2(NC.F2) F3(NC.F3) F10(NC.F10) F12(NC.F12) F13(NC.F13) F14(NC.F14) G1(NC.G1) G2(NC.G2) G3(NC.G3) G10(NC.G10) G12(NC.G12) G13(NC.G13) G14(NC.G14) H1(NC.H1) H2(NC.H2) H3(NC.H3) H5(NC.H5) H12(NC.H12) H13(NC.H13) H14(NC.H14) J1(NC.J1) J2(NC.J2) J3(NC.J3) J5(NC.J5) J12(NC.J12) J13(NC.J13) J14(NC.J14) K1(NC.K1) K2(NC.K2) K3(NC.K3) K6(NC.K6) K7(NC.K7) K10(NC.K10) K12(NC.K12) K13(NC.K13) K14(NC.K14) L1(NC.L1) L2(NC.L2) L3(NC.L3) L12(NC.L12) L13(NC.L13) L14(NC.L14) M1(NC.M1) M2(NC.M2) M3(NC.M3) M7(NC.M7) M8(NC.M8) M9(NC.M9) M10(NC.M10) M11(NC.M11) M12(NC.M12) M13(NC.M13) M14(NC.M14) MA4(NC.MA4) MA6(NC.MA6) MA9(NC.MA9) MA11(NC.MA11) MAE1(NC.MAE1) MAE14(NC.MAE14) MAG2(NC.MAG2) MAG13(NC.MAG13) MAH4(NC.MAH4) MAH6(NC.MAH6) MAH9(NC.MAH9) MAH11(NC.MAH11) MB2(NC.MB2) MB13(NC.MB13) MD1(NC.MD1) MD14(NC.MD14) N1(NC.N1) N3(NC.N3) N6(NC.N6) N7(NC.N7) N8(NC.N8) N9(NC.N9) N10(NC.N10) N11(NC.N11) N12(NC.N12) N13(NC.N13) N14(NC.N14) P1(NC.P1) P2(NC.P2) P7(NC.P7) P8(NC.P8) P9(NC.P9) P10(NC.P10) P11(NC.P11) P12(NC.P12) P13(NC.P13) P14(NC.P14); U18 4(DNU.4) 5(DNU.5) 6(RFU.6) 11(DNU.11) 12(DNU.12) 13(NC.13); U57 10(P6) 11(P7); U58 19(P16); U77 2(NC.2); U78 2(NC.2); U79 2(NC.2); U83 27(NC1)* 28(NC2)* 30(NC3)*; U110 1(NC1); U119 4(P0) 10(P6) 11(P7) 13(P10) 14(P11) 15(P12) 16(P13); U122 2(NC.2) 3(IO1)

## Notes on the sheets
sheet 1
- SH01 - TITLE PAGE
  SH02 - VAYU MCASP
  SH03 - MCASP/VIN6A MUX
  SH04 - VAYU SERIAL I/O
  SH05 - SERIAL I/O MUX
  SH06 - CAN CONNECTORS
  SH07 - SPI FLASH
  SH08 - I2C EEPROM/TEMP SENSOR
  SH09 - NAND FLASH
  SH10 - HPC TOOL
  SH11 - NOR FLASH
  SH12 - eMMC MEMORY
  SH13 - I2C EXPANDER
  SH14 - VAYU SD/MMC IF
  SH15 - SD CARD
  SH16 - VAYU MLB
  SH17 - VAYU ETHERNET
  SH18 - ENET0/VIN4 MUX
  SH19 - VAYU USB
  SH20 - VAYU GPMC
  SH21 - GPMC DATA MUX VIDEO
  SH22 - GPMC ADD MUX VIDEO
  SH23 - GPMC ADD MUX MMC
  SH24 - BOOTSWITCHES
  SH25 - VAYU DDR EMIF1 INTERFACE
  SH26 - VAYU DDR EMIF2 INTERFACE
  SH27 - VAYU HDMI
  SH28 - VAYU VOUT1 PORT LCD
  SH29 - VAYU VIDEO PORTS IN
  SH30 - VIN1 MUX
  SH31 - VIN2 MUX
  SH32 - LCD CONNECTOR
  SH33 - HDMI OUTPUT CONNECTOR
  SH34 - FPD LINK
  SH35 - CAMERA IF
  SH36 - SERDES CLOCK
  SH37 - VAYU SATA/PCIe INTERFACE
  SH38 - PCIe CONNECTORS
  SH39 - VAYU JTAG
  SH40 - VAYU CLOCKS
  SH41 - VAYU INTERNAL LDOS
  SH42 - VAYU IO POWER
  SH43 - VAYU POWER 1V8
  SH44 - VAYU DDR POWER
  SH45 - VAYU 1V8A
- SH46 - VAYU CORE POWER
  SH47 - VAYU GROUND PINS
  SH48 - DDR3 EMIF1 TESTPOINTS
  SH49 - DDR3  BANK 1
  SH50 - DDR3 EMIF1 CAPS
  SH51 - DDR3 BANK1 TERMINATION
  SH52 - TESTPOINTS DDR3  EMIF 2
  SH53 - DDR3 MEMORY BANK 2
  SH54 - DDR3 MEMORY CAPS BANK 2
  SH55 - DDR TERMNATION BANK 2
  SH56 - USB VBUS
  SH57 - USB CONNECTORS
  SH58 - FTDI UART
  SH59 - COM8 LEVEL TRANSLATOR
  SH60 - COM8 CONNECTOR
  SH61 - COM8 POWER
  SH62 - AIC3106
  SH63 - ETHERNET PORT0
  SH64 - ETHERNET PORT1
  SH65 - ETHERNET CONN PORT0 & 1
  SH66 - ETHERNET LEDS
  SH67 - APPLICATION IF CONN1
  SH68 - APPLICATION IF  CONN2
  SH69 - APPLICATION IF  CONN3
  SH70 - PMIC CONTROL
  SH71 - PMIC2
  SH72 - PMIC3
  SH73 - PMIC 4
  SH74 - POWER TPS443351DAP
  SH75 - TPS22965
  SH76 - ETHERNET 2V5
  SH77 - TPS51200
  SH78 - TPS57112 -- 1V5 DDR
  SH79 - CORE POWER ROUTER
  SH80 - POWER ROUTER DDR
  SH81 - POWER ROUTER 1V8
  SH82 - POWER ROUTER 1V8A
  SH83 - POWER ROUTER RTC
  SH84 - POWER ROUTER 3V3
  SH85 - POWER ROUTER EVM
  SH86 - RESET
  SH87 - POWER INPUT
  SH88 - POWER MONITORING ADDRESSES/ETHERNET STRAPPING
  SH89 - CHANGES REV H
- REVISION STATUS OF SHEETS
- REV
- SH
- REV
- G4
- G4
- A
- H
- H
- D1
- H
- G4
- H
- SH
- 81
- 82
- 83
- 84
- 85
- 86
- 87
- 88
- 89
- REV
- H
- D
- D
- H
- A
- H
- G
- A
- H
- H
- SH
- 71
- 72
- 73
- 74
- 75
- 76
- 77
- 78
- 79
- 80
- REV
- D
- F
- H
- H
- A
- A
- A
- A
- A
- G3
- SH
- 61
- 62
- 63
- 64
- 65
- 66
- 67
- 68
- 69
- 70
- REV
- A
- A
- H
- A
- H
- C
- F
- D
- A
- A
- SH
- 51
- 52
- 53
- 54
- 55
- 56
- 57
- 58
- 59
- 60
- REV
- A
- F
- A
- A
- A
- A
- A
- A
- H
- A
- SH
- 41
- 42
- 43
- 44
- 45
- 46
- 47
- 48
- 49
- 50
- REV
- C
- A
- H
- E
- G
- A
- F
- A
- H
- G2
- SH
- 31
- 32
- 33
- 34
- 35
- 36
- 37
- 38
- 39
- 40
- DWN
- R.R.P.
- 12/10/2012
- DATE
- CHK
- DATE
- REV
- A
- E
- D2
- B
- A
- A
- A
- C
- A
- A
- T.W.K.
- 12/10/2012
- ENGR
- DATE
- SH
- 21
- 22
- 23
- 24
- 25
- 26
- 27
- 28
- 29
- 30
- R.R.P.
- 12/10/2012
- ENGR-MGR
- DATE
- REV
- A
- H
- G
- A
- H
- A
- A
- A
- A
- D2
- QA
- R.R.P.
- 12/10/2012
- DATE
- SH
- 11
- 12
- 13
- 14
- 15
- 16
- 17
- 18
- 19
- 20
- C.M.D.
- 12/10/2012
- MFG
- DATE
- REV
- H
- C
- A
- D
- E
- A
- D2
- B
- A
- A
- NEXT ASSY
- USED ON
- R.R.P.
- 12/10/2012
- RLSE
- DATE
- SH
- 1
- 2
- 3
- 4
- 5
- 6
- 7
- 8
- 9
- 10
- APPLICATION
- R.R.P.
- 12/10/2012
sheet 2
- mcasp1_axr[8]
  mcasp1_axr[9]
  mcasp1_axr[10]
  mcasp1_axr[11]
  mcasp1_axr[12]
  mcasp1_axr[13]
  mcasp1_axr[14]
  mcasp1_axr[15]
- mcasp6_axr[0]
  mcasp6_axr[1]
  mcasp6_aclkx
  mcasp6_fsx
  mcasp7_axr[0]
  mcasp7_axr[1]
  mcasp7_aclkx
  mcasp7_fsx
- vin6a_d[15]
  vin6a_d[14]
  vin6a_d[13]
  vin6a_d[12]
  vin6a_d[11]
  vin6a_d[10]
  vin6a_d[9]
  vin6a_d[8]
- gpio5_4
  gpio5_5
  gpio5_6
  gpio5_7
  gpio5_8
  gpio5_9
  gpio5_10
  gpio5_11
  gpio5_12
  gpio4_17
  gpio4_18
  gpio6_4
  gpio6_5
  gpio6_6
- mcasp1_axr[2]
  mcasp1_axr[3]
  mcasp1_axr[4]
  mcasp1_axr[5]
  mcasp1_axr[6]
  mcasp1_axr[7]
  mcasp1_axr[8]
  mcasp1_axr[9]
  mcasp1_axr[10]
  mcasp1_axr[11]
  mcasp1_axr[12]
  mcasp1_axr[13]
  mcasp1_axr[14]
  mcasp1_axr[15]
- mcasp1_axr[12]
  mcasp1_axr[13]
  mcasp1_axr[14]
  mcasp1_axr[15]
- mcasp7_axr[0]
  mcasp7_axr[1]
  mcasp7_aclkx
  mcasp7_fsx
- vin6a_d[11]
  vin6a_d[10]
  vin6a_d[9]
  vin6a_d[8]
- mcasp2_aclkx
  mcasp2_fsx
  mcasp2_aclkr
  mcasp2_fsr
  mcasp2_axr[0]
  mcasp2_axr[1]
  mcasp2_axr[2]
  mcasp2_axr[3]
  mcasp2_axr[4]
  mcasp2_axr[5]
  mcasp2_axr[6]
  mcasp2_axr[7]
- vin6a_d[7]
  vin6a_d[6]
  vin6a_d[5]
  vin6a_d[4]
- mcasp3_aclkx
  mcasp3_fsx
  mcasp3_axr[0]
  mcasp3_axr[1]
- vin6a_d[3]
  vin6a_d[2]
  vin6a_d[1]
  vin6a_d[0]
- mcasp4_aclkx
  mcasp4_fsx
  mcasp4_axr[0]
  mcasp4_axr[1]
  McASP5
  mcasp5_aclkx
  mcasp5_fsx
  mcasp5_axr[0]
  mcasp5_axr[1]
- vin5a_d[15]
  vin5a_d[14]
  vin5a_d[13]
  vin5a_d[12]
  vin5a_d[11]
  vin5a_d[10]
  vin5a_d[9]
  vin5a_d[8]
- mcasp5_aclkx
  mcasp5_fsx
  mcasp5_axr[0]
  mcasp5_axr[1]
- mlb_clk
  mlb_sig
  mlb_dat
- mcasp1_aclkx
  mcasp1_fsx
  mcasp1_aclkr
  mcasp1_fsr
  mcasp1_axr[0]
  mcasp1_axr[1]
- vin6a_fld0
  vin6a_de0
  vin6a_vsync0
  vin6a_hsync0
- xref_clk2
- mcasp3_ahclkx
- xref_clk1
- mcasp6_ahclkx
- vin6a_clk0
sheet 3
- HVDA541QDRQ1
sheet 4
- ROUTE THE FOLLOWING SIGNALS AS A GROUP
  WITH A NET LENGTH LESS THEN 2.75
  INCHES AND 60ps OF SKEW.  PLACE THE
  DUAL RESISTOR CLOSE TOGETHER NEAR THE
  PIN OF THE FLASH.
- AQSPI1_SCLK
  AQSPI1_RTCLK
  AQSPI1_CS[0]
  AQSPI1_D[0]
  AQSPI1_D[1]
  AQSPI1_D[2]
  AQSPI1_D[3]
- R729/R444
- R730/R132
- SWAP ON REV D
sheet 6
- BLANK REMOVED
sheet 7
- MAKE SURE ADDRESS LINE A1 IS THE 16
  BIT ADDRESS LINE, IT SHOULD BE
sheet 8
- ER23
- ER40
- ER21
- REV G
- DUAL FOOTPRINT 153/169 USES 153 PIN
  NUMBERS FOR COMPATIBLE PINS.
sheet 9
- REV E
- REV E
- REV G
- REVC-DR1
- REV E
- REV D
- REVC-DR1
sheet 10
- ER41
- DR31
- REV E
- ~97 micro second ramp
sheet 11
- PLACE 100 OHM RESISTORS AT CPU
- 100 ohm diff pairs
- GP1[5] REPLACED
sheet 12
- mdio_mclk
  mdio_d
  RMII_MHZ_50_CLK
  uart3_rxd
  uart3_txd
  rgmii0_txc
  rgmii0_txctl
  rgmii0_txd[3]
  rgmii0_txd[2]
  rgmii0_txd[1]
  rgmii0_txd[0]
  rgmii0_rxc
  rgmii0_rxctl
  rgmii0_rxd[3]
  rgmii0_rxd[2]
  rgmii0_rxd[1]
  rgmii0_rxd[0]
- vin4b_clk1
  vin4b_d[0]
  vin4b_d[1]
  vin4b_d[2]
  vin4b_d[3]
  vin4b_d[4]
  vin4b_de1
  vin4b_hsync1
  vin4b_vsync1
  vin4b_d[5]
  vin4b_d[6]
  vin4b_d[7]
  vin4b_fld1
